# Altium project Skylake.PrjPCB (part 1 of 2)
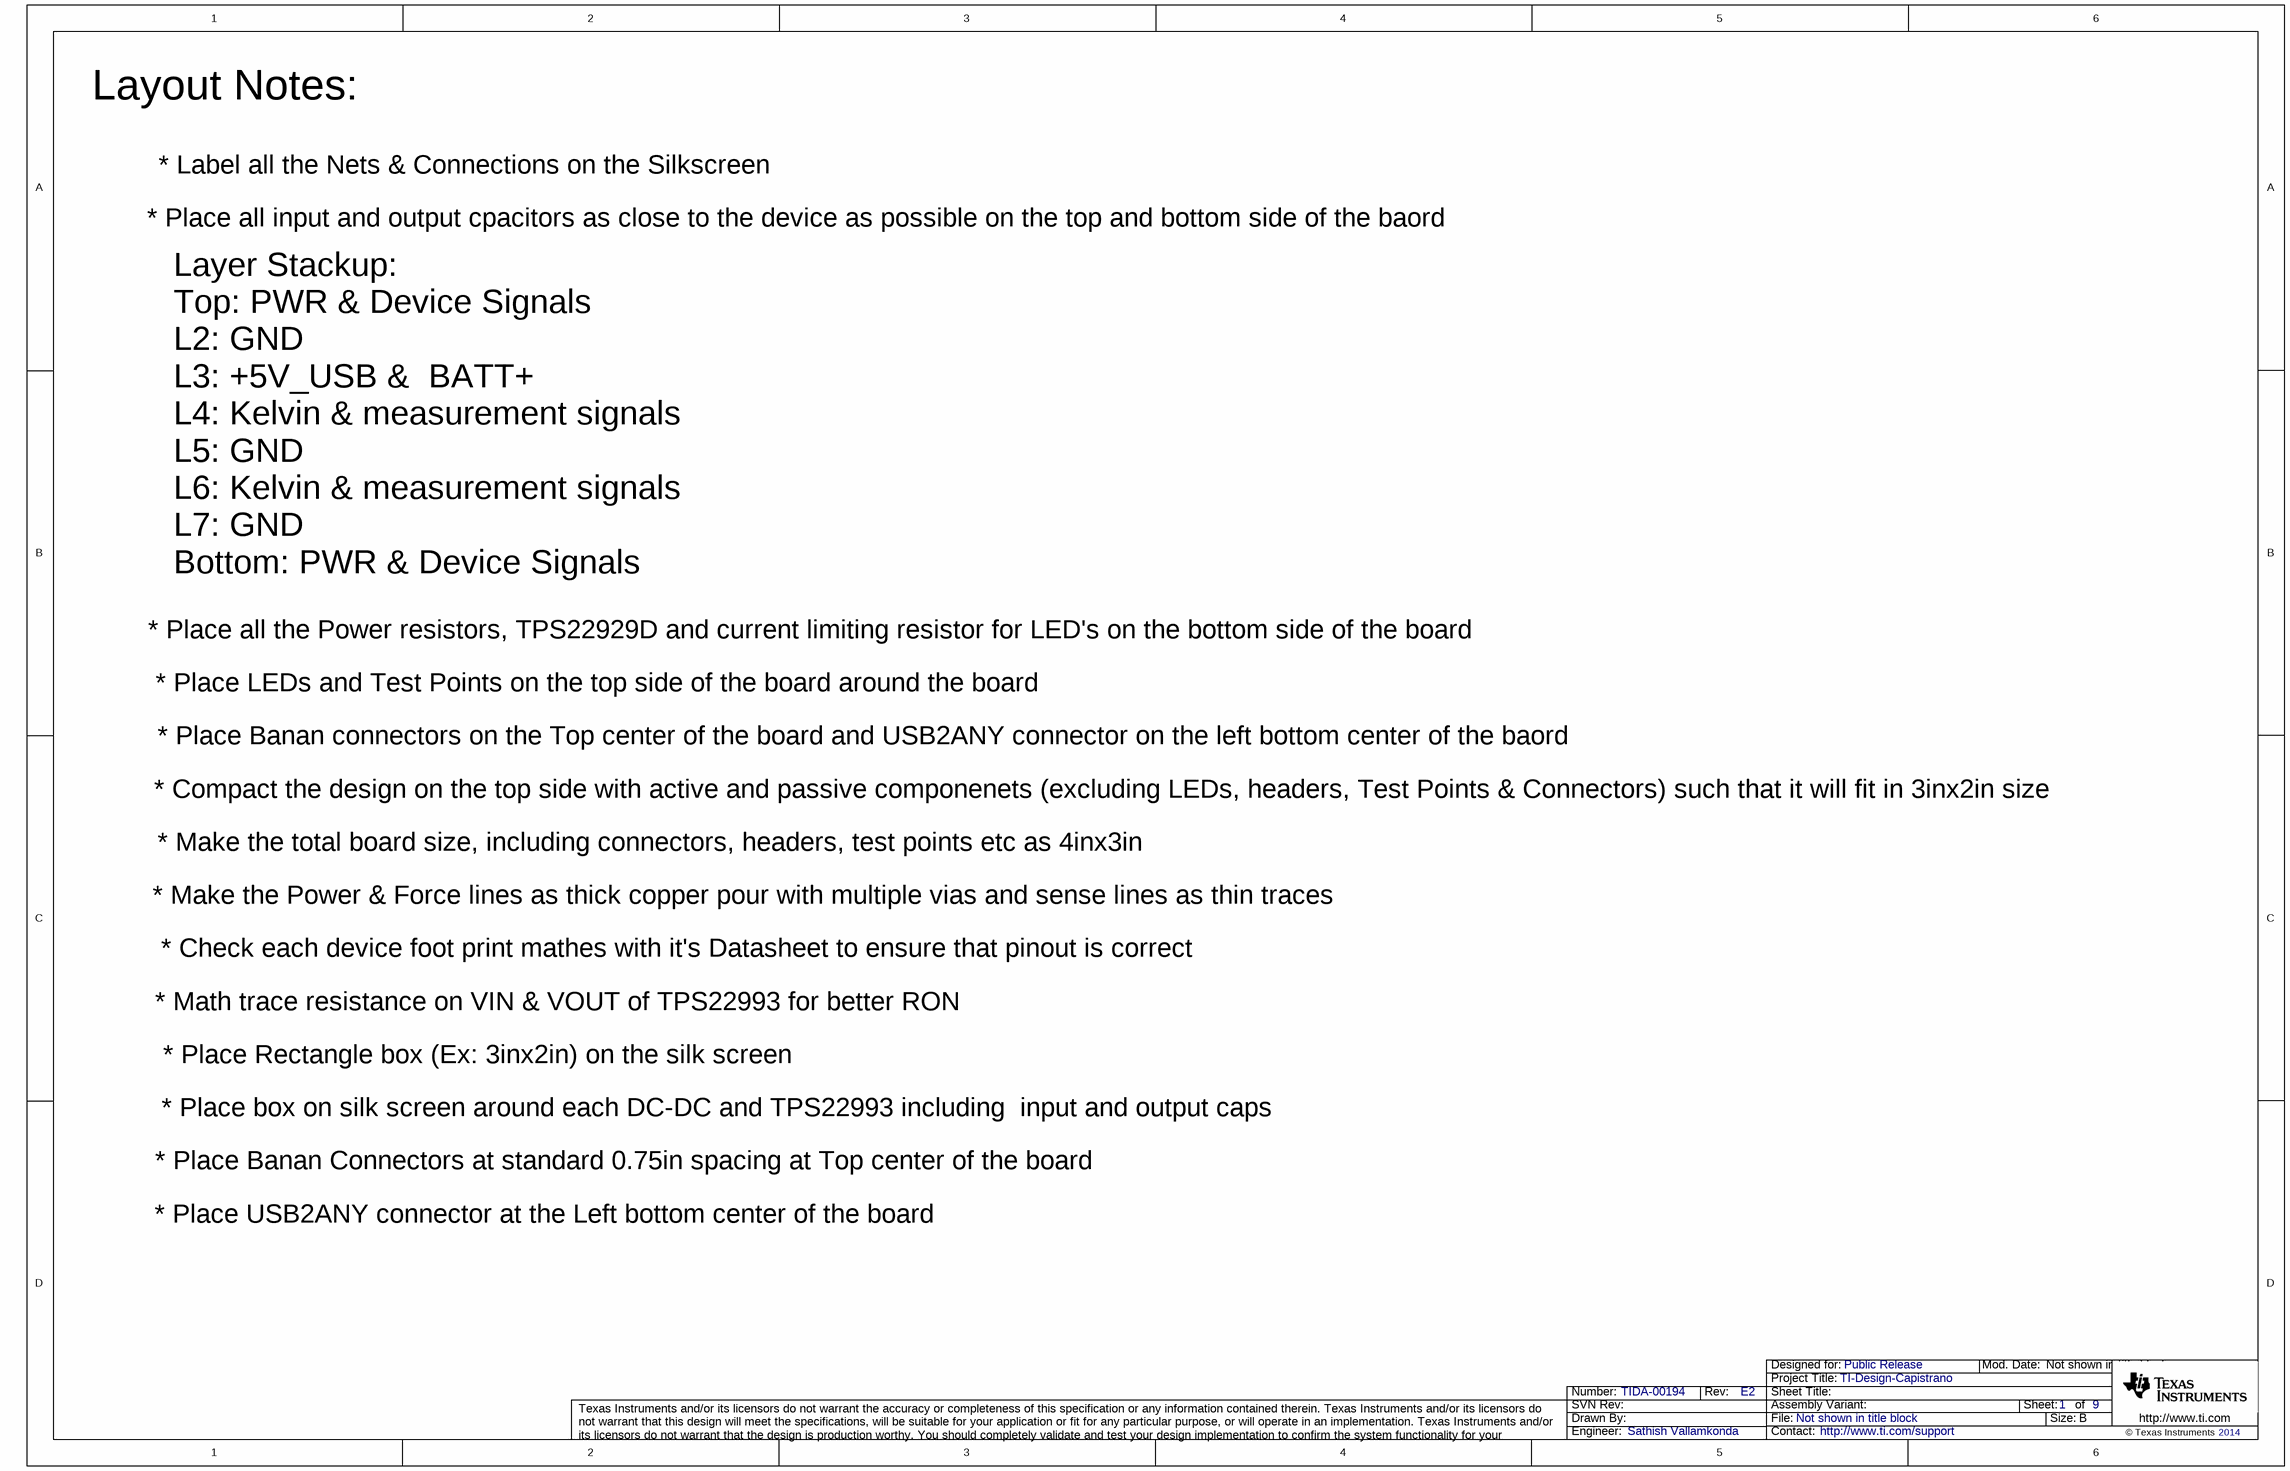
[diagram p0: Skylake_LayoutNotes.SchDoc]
CopyrightYear: 2014; PCB_Layout: Pactron; PCB_Rev: E2; PRJ_Customer: Public Release; PRJ_Engineer: Sathish Vallamkonda; PRJ_Number: TIDA-00194; PRJ_Title: TI-Design-Capistrano; SCH_Rev: E2; TechSupport: http://www.ti.com/support
9 sheets, 344 parts. Net scope: flat (ports and power ports of the same name join across sheets).
Board file: Skylake.PcbDoc
Sheets:
  Skylake_LayoutNotes.SchDoc
  Skylake_Hardware.SchDoc
  Skylake_USB2ANY_connections.SchDoc
  Skylake_TPS22993_U1_U2.SchDoc
  Skylake_TPS22993_U3_U4.SchDoc
  Skylake_TPS22993_U5_U6.SchDoc
  Skylake_TPS22993_U7.SchDoc
  Skylake_LEDs_1.SchDoc
  Skylake_LEDs_2.SchDoc

## Sheet Skylake_LayoutNotes.SchDoc
size 431 x 279 mm; Date: Not shown in title block; ApprovedBy: Not shown in title block; CheckedBy: Not shown in title block; Author: Not shown in title block; CompanyName: Not shown in title block; Engineer: Not shown in title block; Organization: Not shown in title block; Address1: Not shown in title block; Address2: Not shown in title block; Address3: Not shown in title block; Address4: Not shown in title block; DocumentNumber: 1; Revision: Use project parameter SCH_Rev; SheetNumber: 1; SheetTotal: 9; PageSetup: Record=PageOptions|CenterHorizontal=True|CenterVertical=True|PrintScale=1.00|XCorrection=1.00|YCorrection=1.00|PrintKind=0|BorderSize=5000000|LeftOffset=0|BottomOffset=0|Orientation=2|PaperLength=1000|PaperWidth=1000|Scale=100|PaperSource=15|PrintQuality=600|MediaType=1|DitherType=10|PaperKind=Letter|PrintScaleMode=1

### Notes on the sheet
- Layout Notes:
- * Label all the Nets & Connections on the Silkscreen
- * Place all input and output cpacitors as close to the device as possible on the top and bottom side of the baord
- Layer Stackup:
  Top: PWR & Device Signals
  L2: GND
  L3: +5V_USB &  BATT+
  L4: Kelvin & measurement signals
  L5: GND
  L6: Kelvin & measurement signals
  L7: GND
  Bottom: PWR & Device Signals
- * Place all the Power resistors, TPS22929D and current limiting resistor for LED's on the bottom side of the board
- * Place LEDs and Test Points on the top side of the board around the board
- * Place Banan connectors on the Top center of the board and USB2ANY connector on the left bottom center of the baord
- * Compact the design on the top side with active and passive componenets (excluding LEDs, headers, Test Points & Connectors) such that it will fit in 3inx2in size
- * Make the total board size, including connectors, headers, test points etc as 4inx3in
- * Make the Power & Force lines as thick copper pour with multiple vias and sense lines as thin traces
- * Check each device foot print mathes with it's Datasheet to ensure that pinout is correct
- * Math trace resistance on VIN & VOUT of TPS22993 for better RON
- * Place Rectangle box (Ex: 3inx2in) on the silk screen
- * Place Banan Connectors at standard 0.75in spacing at Top center of the board
- * Place box on silk screen around each DC-DC and TPS22993 including  input and output caps
- * Place USB2ANY connector at the Left bottom center of the board

## Sheet Skylake_Hardware.SchDoc
size 431 x 279 mm; Date: Not shown in title block; ApprovedBy: Not shown in title block; CheckedBy: Not shown in title block; Author: Not shown in title block; CompanyName: Not shown in title block; Engineer: Not shown in title block; Organization: Not shown in title block; Address1: Not shown in title block; Address2: Not shown in title block; Address3: Not shown in title block; Address4: Not shown in title block; DocumentNumber: 1; Revision: Use project parameter SCH_Rev; SheetNumber: 2; SheetTotal: 9; PageSetup: Record=PageOptions|CenterHorizontal=True|CenterVertical=True|PrintScale=1.00|XCorrection=1.00|YCorrection=1.00|PrintKind=0|BorderSize=5000000|LeftOffset=0|BottomOffset=0|Orientation=2|PaperLength=1000|PaperWidth=1000|Scale=100|PaperSource=15|PrintQuality=600|MediaType=1|DitherType=10|PaperKind=Letter|PrintScaleMode=1
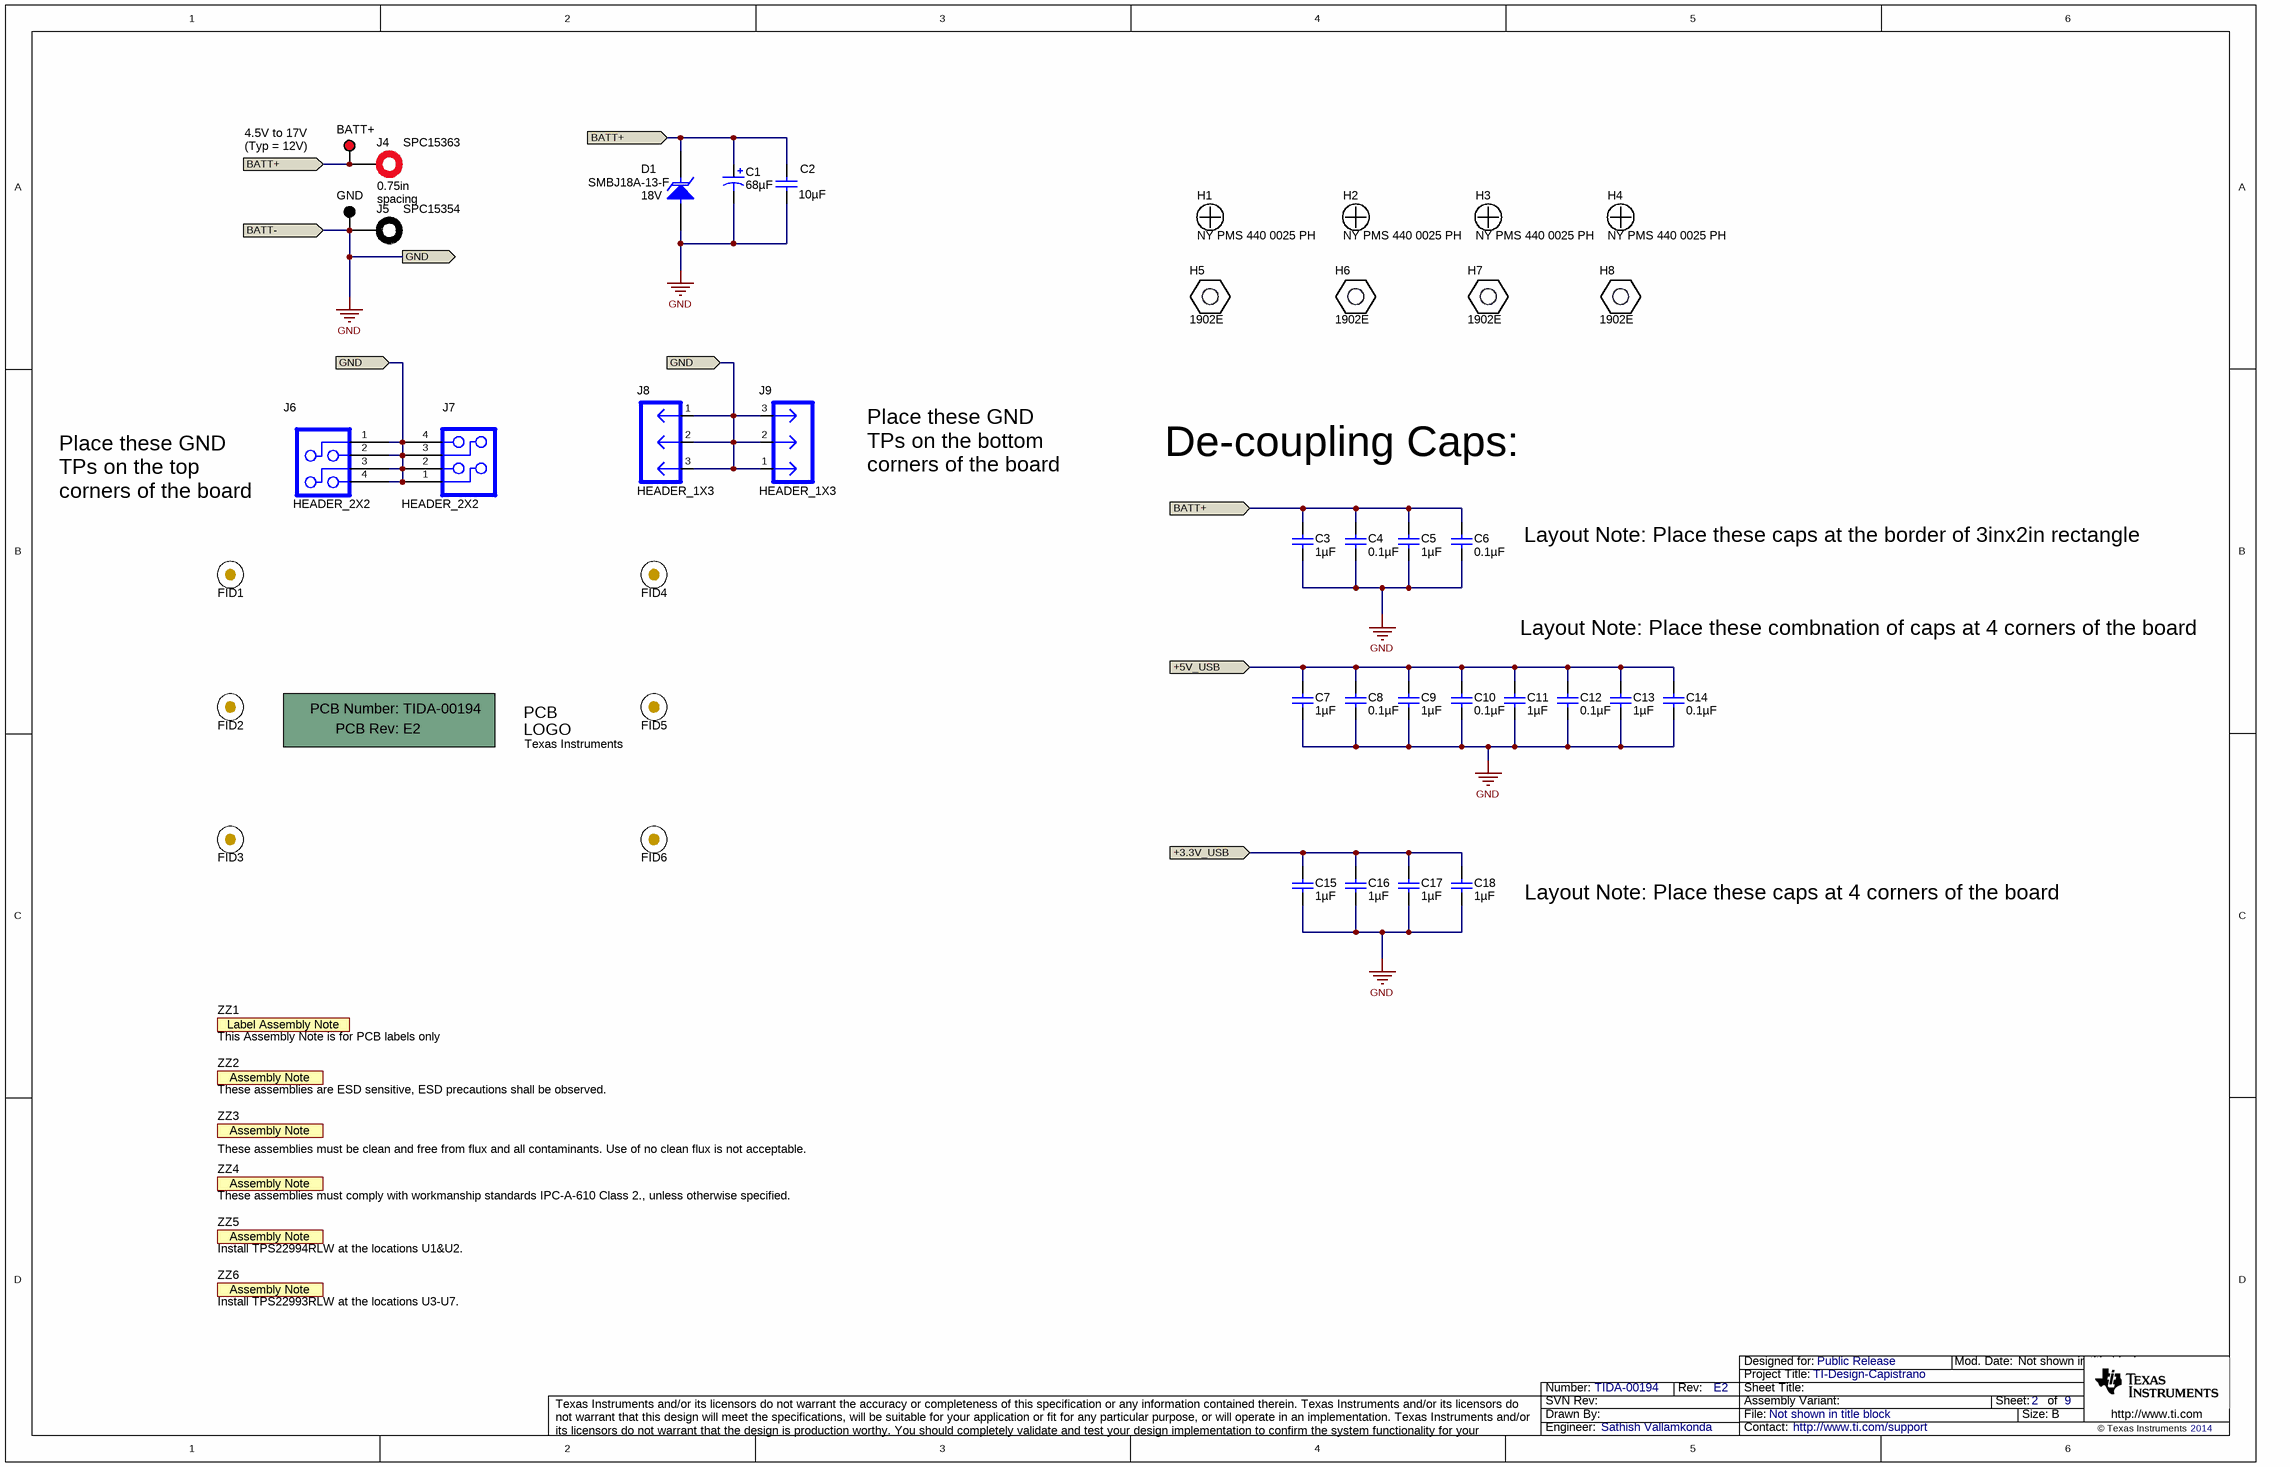
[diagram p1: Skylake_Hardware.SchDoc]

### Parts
!PCB  Printed Circuit Board  (value not drawn)  (mechanical)
BATT+  5005  [Keystone5005]  (value not drawn)
C1  ValueDisplayed: 68µF  [7361-38]  (hidden comment: TPSV686M035R0150)
C2  ValueDisplayed: 10µF  [1210]  (hidden comment: C3225X6S1V106K250AC)
C3  ValueDisplayed: 1µF  [0805_HV]  (hidden comment: C1608X7R1V105K080AC)
C4  ValueDisplayed: 0.1µF  [0805_HV]  (hidden comment: Taiyo Yuden)
C5  ValueDisplayed: 1µF  [0805_HV]  (hidden comment: C1608X7R1V105K080AC)
C6  ValueDisplayed: 0.1µF  [0805_HV]  (hidden comment: Taiyo Yuden)
C7  ValueDisplayed: 1µF  [0805_HV]  (hidden comment: 0805ZC105KAT2A)
C8  ValueDisplayed: 0.1µF  [0603]  (hidden comment: C0603C104K8RACTU)
C9  ValueDisplayed: 1µF  [0805_HV]  (hidden comment: 0805ZC105KAT2A)
C10  ValueDisplayed: 0.1µF  [0603]  (hidden comment: C0603C104K8RACTU)
C11  ValueDisplayed: 1µF  [0805_HV]  (hidden comment: 0805ZC105KAT2A)
C12  ValueDisplayed: 0.1µF  [0603]  (hidden comment: C0603C104K8RACTU)
C13  ValueDisplayed: 1µF  [0805_HV]  (hidden comment: 0805ZC105KAT2A)
C14  ValueDisplayed: 0.1µF  [0603]  (hidden comment: C0603C104K8RACTU)
C15  ValueDisplayed: 1µF  [0805_HV]  (hidden comment: 0805ZC105KAT2A)
C16  ValueDisplayed: 1µF  [0805_HV]  (hidden comment: 0805ZC105KAT2A)
C17  ValueDisplayed: 1µF  [0805_HV]  (hidden comment: 0805ZC105KAT2A)
C18  ValueDisplayed: 1µF  [0805_HV]  (hidden comment: 0805ZC105KAT2A)
D1  SMBJ18A-13-F  value 18V  [SMB]
FID1  Fiducial  [Fiducial10-20]  (value not drawn)
FID2  Fiducial  [Fiducial10-20]  (value not drawn)
FID3  Fiducial  [Fiducial10-20]  (value not drawn)
FID4  Fiducial  [Fiducial10-20]  (value not drawn)
FID5  Fiducial  [Fiducial10-20]  (value not drawn)
FID6  Fiducial  [Fiducial10-20]  (value not drawn)
GND  5006  [Keystone5006]  (value not drawn)
H1  NY PMS 440 0025 PH  [NY PMS 440 0025 PH]
H2  NY PMS 440 0025 PH  [NY PMS 440 0025 PH]
H3  NY PMS 440 0025 PH  [NY PMS 440 0025 PH]
H4  NY PMS 440 0025 PH  [NY PMS 440 0025 PH]
H5  1902E  [Keystone_1902E]
H6  1902E  [Keystone_1902E]
H7  1902E  [Keystone_1902E]
H8  1902E  [Keystone_1902E]
J4  SPC15363  [Tenma_SPC15363]
J5  SPC15354  [Tenma_SPC15354]
J6  HEADER_2X2  [HDR_2X2]
J7  HEADER_2X2  [HDR_2X2]
J8  HEADER_1X3  [HDR100_1X3]
J9  HEADER_1X3  [HDR100_1X3]
Logo1  Texas Instruments  [TI_Stacked_Overlay_Small]  (no BOM)
ZZ1  This Assembly Note is for PCB labels only  [AssemblyNoteLabel]  (no BOM)
ZZ2  These assemblies are ESD sensitive, ESD precautions shall be observed.  [AssemblyNote]  (no BOM)
ZZ3  These assemblies must be clean and free from flux and all contaminants. Use of no clean flux is not acceptable.  [AssemblyNote]  (no BOM)
ZZ4  These assemblies must comply with workmanship standards IPC-A-610 Class 2., unless otherwise specified.  [AssemblyNote]  (no BOM)
ZZ5  Install TPS22994RLW at the locations U1&U2.  [AssemblyNote]  (no BOM)
ZZ6  Install TPS22993RLW at the locations U3-U7.  [AssemblyNote]  (no BOM)

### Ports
+3.3V_USB (in), +5V_USB (in), BATT+ (in), BATT- (in), GND (in), GND (out)

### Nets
GND: C1.2(-) C2.2 C3.2 C4.2 C5.2 C6.2 C7.2 C8.2 C9.2 C10.2 C11.2 C12.2 C13.2 C14.2 C15.2 C16.2 C17.2 C18.2 D1.2(A) GND.1 J5.1 J6.1 J6.2 J6.3 J6.4 J7.1 J7.2 J7.3 J7.4 J8.1 J8.2 J8.3 J9.1 J9.2 J9.3 ; port BATT-, port GND
+3.3V_USB: C15.1 C16.1 C17.1 C18.1 ; port +3.3V_USB
+5V_USB: C7.1 C8.1 C9.1 C10.1 C11.1 C12.1 C13.1 C14.1 ; port +5V_USB
BATT+: BATT+.1 C1.1(+) C2.1 C3.1 C4.1 C5.1 C6.1 D1.1(K) J4.1 ; port BATT+

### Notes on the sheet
- (near BATT+) 4.5V to 17V
  (Typ = 12V)
- (near J4) 0.75in spacing
- Place these GND TPs on the bottom corners of the board
- De-coupling Caps:
- Place these GND TPs on the top corners of the board
- (near C6) Layout Note: Place these caps at the border of 3inx2in rectangle
- Layout Note: Place these combnation of caps at 4 corners of the board
- (near C18) Layout Note: Place these caps at 4 corners of the board

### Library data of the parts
!PCB = PCB: Manufacturer: Any; PartNumber: TIDA-00194; SymbolCreator: a0412235
BATT+ = 5005: Test Point, Compact, Red, TH; Manufacturer: Keystone; CompType: Test Point Loop; U/M: EA
C1 = TPSV686M025R0095: CAP, TA, 68uF, 35V, +/-20%, 0.095 ohm, SMD; Manufacturer: AVX; Polarized: Y; CompType: Capacitor; U/M: EA; Cap_F: 0.000068; Tolerance_%: 20; VDC_V: 35; ESR_Ohm: 0.095; IRMS_A: 1.46; TaMin_C: -55; TaMax_C: 125; Cap_Case: V
C2 = GRM32DR61E106KA12L: CAP, CERM, 10uF, 35V, +/-10%, X5R, 1210; Manufacturer: TDK Corporation; Polarized: N; CompType: Capacitor; U/M: EA; Cap_F: 0.00001; Tolerance_%: 10; Value1: Unknown; VDC_V: 35; TaMin_C: -55; TaMax_C: 85
C3 C5 = GRM21BR61E226ME44: CAP, CERM, 1uF, 35V, +/-20%, X5R, 0805; Manufacturer: TDK Corporation; Polarized: N; CompType: Capacitor; U/M: EA; Cap_F: 0.000022; Tolerance_%: 20; Value1: Unknown; VDC_V: 35; TaMin_C: -55; TaMax_C: 85; Cap_Case: 0805
C4 C6 = GRM21BR61E226ME44: CAP, CERM, 0.1uF, 35V, +/-20%, X5R, 0603; Manufacturer: TDK Corporation; Polarized: N; CompType: Capacitor; U/M: EA; Tolerance_%: 20; Value1: Unknown; VDC_V: 35; TaMin_C: -55; TaMax_C: 85; Cap_Case: 0603
C7 C9 C11 C13 C15-C18 = 0805ZC105KAT2A: CAP, CERM, 1uF, 10V, +/-10%, X7R, 0805; Manufacturer: AVX; Polarized: N; CompType: Capacitor; U/M: EA; Cap_F: 0.000001; Tolerance_%: 10; ESR_Ohm: 0.008; Value1: 0.008 ohm; TaMin_C: -55; TaMax_C: 125; Cap_Case: 0805
C8 C10 C12 C14 = GRM188R71C104KA01D: CAP, CERM, 0.1uF, 10V, +/-10%, X7R, 0603; Manufacturer: Kemet; Polarized: N; CompType: Capacitor; U/M: EA; Cap_F: 0.0000001; Tolerance_%: 10; Value1: Unknown; TaMin_C: -55; TaMax_C: 125
D1 = SMBJ18A-13-F: Diode, TVS, Uni, 18V, 600W, SMB; Manufacturer: Diodes Inc.; U/M: EA; Power_W: 5; Vr_V: 18; Value1: 5W
FID1-FID6 = Fiducial: Fiducial mark.  There is nothing to buy or mount.; SymbolCreator: codlsc
GND = 5006: Test Point, Compact, Black, TH; Manufacturer: Keystone; CompType: Test Point Loop; U/M: EA
H1-H4 = NY PMS 440 0025 PH: Machine Screw, Round, #4-40 x 1/4, Nylon, Philips panhead; Manufacturer: B&F Fastener Supply; CompType: Hardware; SymbolCreator: codlsc; U/M: EA
H5-H8 = 1902E: Standoff, Hex, 1"L #4-40 Nylon; Manufacturer: Keystone; SymbolCreator: a0412235; CompType: Hardware
J4 = SPC15363: BANANA JACK, SOLDER LUG, RED, TH; Manufacturer: Tenma; SymbolCreator: a0412235; U/M: EA
J5 = SPC15354: BANANA JACK, SOLDER LUG, BLACK, TH; Manufacturer: Tenma; SymbolCreator: a0412235; U/M: EA
J6 J7 = HEADER_2X2: Header, 2x2-pin, 100mil spacing; Manufacturer: Sullins; PartNumber: PEC02DAAN; area: 40000; Value: PEC02DAAN
J8 J9 = HEADER_1X3: Header, Male 3-pin, 100mil spacing,; Manufacturer: Sullins; PartNumber: PEC03SAAN; area: 30000; Value: PEC03SAAN
Logo1 = TI_Logo: Texas Instrument Corporate Signature; SymbolCreator: codlsc
ZZ1 = AssemblyNoteLabel: SymbolCreator: a0412235
ZZ2-ZZ4 = AssemblyNote: SymbolCreator: codlsc
ZZ5 ZZ6 = AssemblyNote: These assemblies must comply with workmanship standards IPC-A-610 Class 2., unless otherwise specified.; SymbolCreator: codlsc

## Sheet Skylake_USB2ANY_connections.SchDoc
size 431 x 279 mm; Date: Not shown in title block; ApprovedBy: Not shown in title block; CheckedBy: Not shown in title block; Author: Not shown in title block; CompanyName: Not shown in title block; Engineer: Not shown in title block; Organization: Not shown in title block; Address1: Not shown in title block; Address2: Not shown in title block; Address3: Not shown in title block; Address4: Not shown in title block; DocumentNumber: 1; Revision: Use project parameter SCH_Rev; SheetNumber: 3; SheetTotal: 9; PageSetup: Record=PageOptions|CenterHorizontal=True|CenterVertical=True|PrintScale=1.00|XCorrection=1.00|YCorrection=1.00|PrintKind=0|BorderSize=5000000|LeftOffset=0|BottomOffset=0|Orientation=2|PaperLength=1000|PaperWidth=1000|Scale=100|PaperSource=15|PrintQuality=600|MediaType=1|DitherType=10|PaperKind=Letter|PrintScaleMode=1
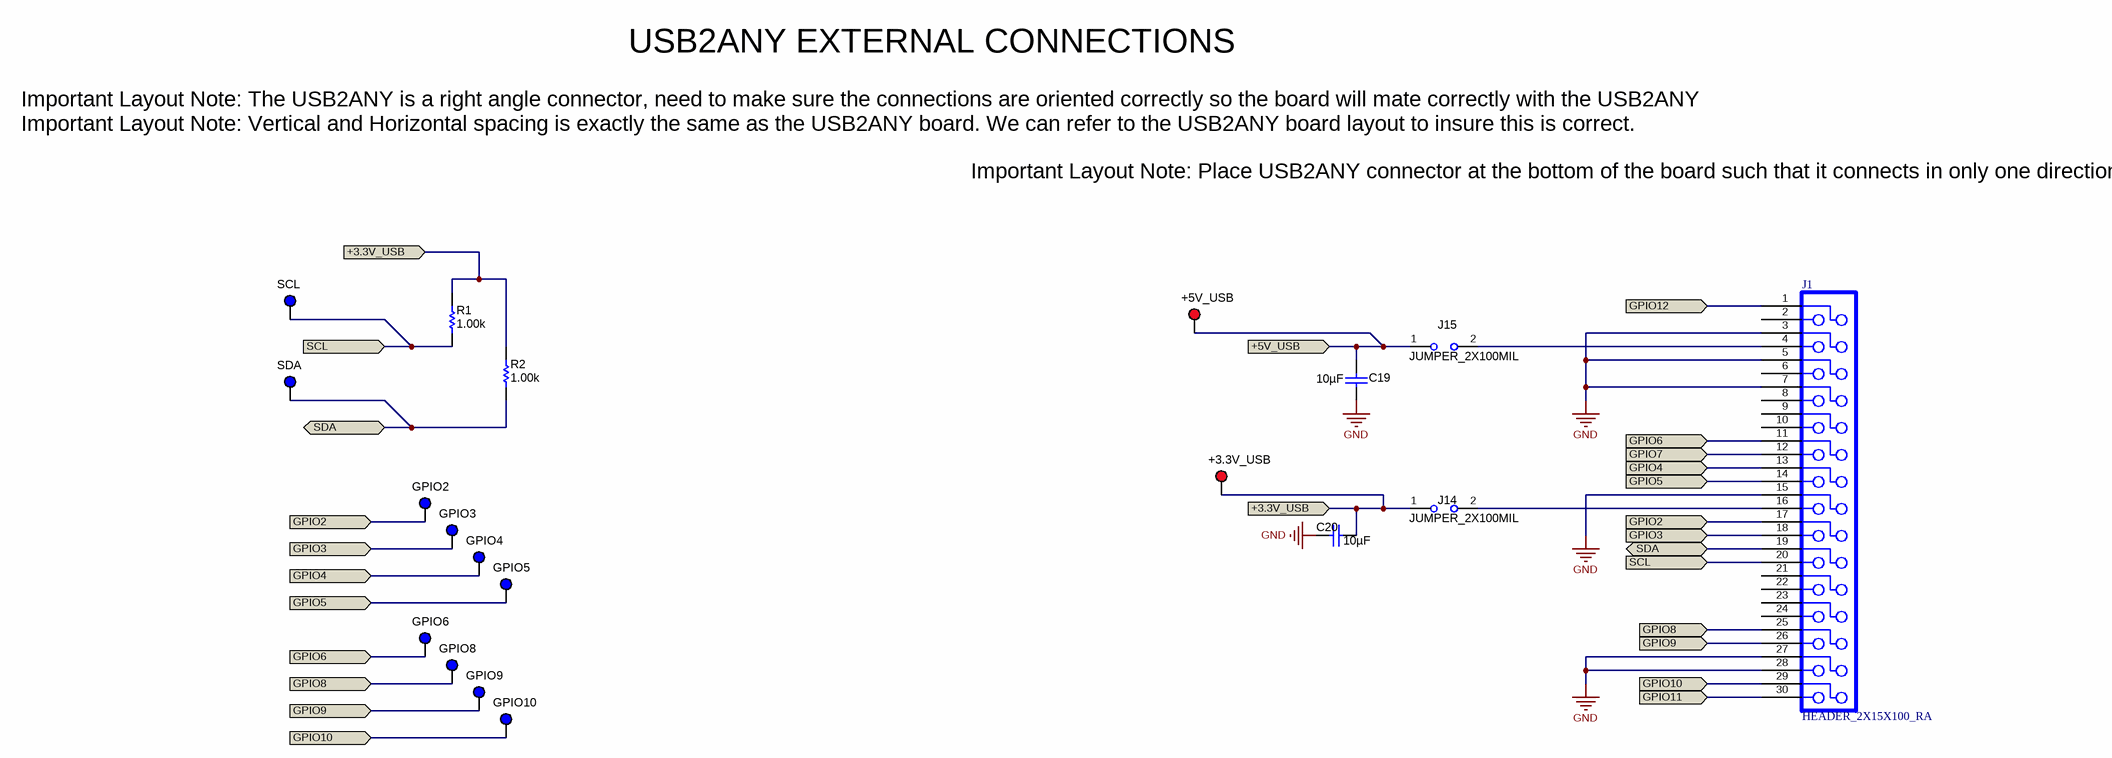
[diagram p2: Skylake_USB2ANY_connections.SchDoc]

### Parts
+3.3V_USB  5005  [Keystone5005]  (value not drawn)
+5V_USB  5005  [Keystone5005]  (value not drawn)
C19  ValueDisplayed: 10µF  [0805_HV]  (hidden comment: C0805C106K8PACTU)
C20  ValueDisplayed: 10µF  [0805_HV]  (hidden comment: C0805C106K8PACTU)
GPIO2  5122  [Keystone5122]  (value not drawn)
GPIO3  5122  [Keystone5122]  (value not drawn)
GPIO4  5122  [Keystone5122]  (value not drawn)
GPIO5  5122  [Keystone5122]  (value not drawn)
GPIO6  5122  [Keystone5122]  (value not drawn)
GPIO8  5122  [Keystone5122]  (value not drawn)
GPIO9  5122  [Keystone5122]  (value not drawn)
GPIO10  5122  [Keystone5122]  (value not drawn)
J1  HEADER_2X15X100_RA  [2530-5002UB]
J14  JUMPER_2X100MIL  [HDR100_1X2]
J15  JUMPER_2X100MIL  [HDR100_1X2]
R1  value 1.00k  [0402]  (hidden comment: CRCW04021K00FKED)
R2  value 1.00k  [0402]  (hidden comment: CRCW04021K00FKED)
SCL  5122  [Keystone5122]  (value not drawn)
SDA  5122  [Keystone5122]  (value not drawn)

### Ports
+3.3V_USB (in), +5V_USB (in), GPIO2 (in), GPIO3 (in), GPIO4 (in), GPIO5 (in), GPIO6 (in), GPIO7 (in), GPIO8 (in), GPIO9 (in), GPIO10 (in), GPIO11 (in), GPIO12 (in), SCL (in), SDA (bidir)

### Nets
GND: C19.2 C20.2 J1.3 J1.5 J1.7 J1.15 J1.27 J1.28
+3.3V_USB: +3.3V_USB.1 C20.1 J14.1 R1.2 R2.2 ; port +3.3V_USB
+5V_USB: +5V_USB.1 C19.1 J15.1 ; port +5V_USB
GPIO2: GPIO2.1 J1.17 ; port GPIO2
GPIO3: GPIO3.1 J1.18 ; port GPIO3
GPIO4: GPIO4.1 J1.13 ; port GPIO4
GPIO5: GPIO5.1 J1.14 ; port GPIO5
GPIO6: GPIO6.1 J1.11 ; port GPIO6
GPIO7: J1.12 ; port GPIO7
GPIO8: GPIO8.1 J1.25 ; port GPIO8
GPIO9: GPIO9.1 J1.26 ; port GPIO9
GPIO10: GPIO10.1 J1.29 ; port GPIO10
GPIO11: J1.30 ; port GPIO11
GPIO12: J1.1 ; port GPIO12
SCL: J1.20 R1.1 SCL.1 ; port SCL
SDA: J1.19 R2.1 SDA.1 ; port SDA
NetJ1_4: J1.4 J15.2
NetJ1_16: J1.16 J14.2

Not connected (* = marked no-connect by the designer): J1 2 6 8 9 10 21 22 23 24

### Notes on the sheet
- USB2ANY EXTERNAL CONNECTIONS
- Important Layout Note: The USB2ANY is a right angle connector, need to make sure the connections are oriented correctly so the board will mate correctly with the USB2ANY
  Important Layout Note: Vertical and Horizontal spacing is exactly the same as the USB2ANY board. We can refer to the USB2ANY board layout to insure this is correct.
- Important Layout Note: Place USB2ANY connector at the bottom of the board such that it connects in only one direction

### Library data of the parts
+3.3V_USB +5V_USB = 5005: as BATT+ on sheet Skylake_Hardware
C19 C20 = C0805C106K8PACTU: CAP, CERM, 10uF, 10V, +/-10%, X5R, 0805; Manufacturer: Kemet; Polarized: N; CompType: Capacitor; U/M: EA; Cap_F: 0.00001; Tolerance_%: 10; ESR_Ohm: 0.003; Value1: 0.003 ohm; IRMS_A: 11.43; TaMin_C: -55; TaMax_C: 85; Cap_Case: 0805
GPIO2-GPIO6 GPIO8-GPIO10 SCL SDA = 5122: Test Point, Compact, Blue, TH; Manufacturer: Keystone; CompType: Test Point Loop; U/M: EA
J1 = HEADER_2X15X100_RA: Header, Male 2x15-pin,  100mil spacing (36-pin strip), Right-Angle; Manufacturer: 3M; area: 872100; Value: 2530-5002UB
J14 J15 = JUMPER_2X100MIL: Header, Male 2-pin, 100mil spacing,; Manufacturer: Sullins; PartNumber: PEC02SAAN; area: 20000; Value: PEC02SAAN
R1 R2 = CRCW04021K00FKED: RES, 1.00k ohm, 1%, 0.063W, 0402; Manufacturer: Vishay-Dale; CompType: Resistor; Res_ohm: 1000; Value_Code: 1k00; Tolerance_%: 1; Power_W: 0.063; VDC_V: 50; TempCo: 100 ppm/C; EIA_Code: E96; U/M: EA

## Sheet Skylake_TPS22993_U1_U2.SchDoc
size 431 x 279 mm; Date: Not shown in title block; ApprovedBy: Not shown in title block; CheckedBy: Not shown in title block; Author: Not shown in title block; CompanyName: Not shown in title block; Engineer: Not shown in title block; Organization: Not shown in title block; Address1: Not shown in title block; Address2: Not shown in title block; Address3: Not shown in title block; Address4: Not shown in title block; DocumentNumber: 1; Revision: Use project parameter SCH_Rev; SheetNumber: 4; SheetTotal: 9; PageSetup: Record=PageOptions|CenterHorizontal=True|CenterVertical=True|PrintScale=1.00|XCorrection=1.00|YCorrection=1.00|PrintKind=0|BorderSize=5000000|LeftOffset=0|BottomOffset=0|Orientation=2|PaperLength=1000|PaperWidth=1000|Scale=100|PaperSource=15|PrintQuality=600|MediaType=1|DitherType=10|PaperKind=Letter|PrintScaleMode=1
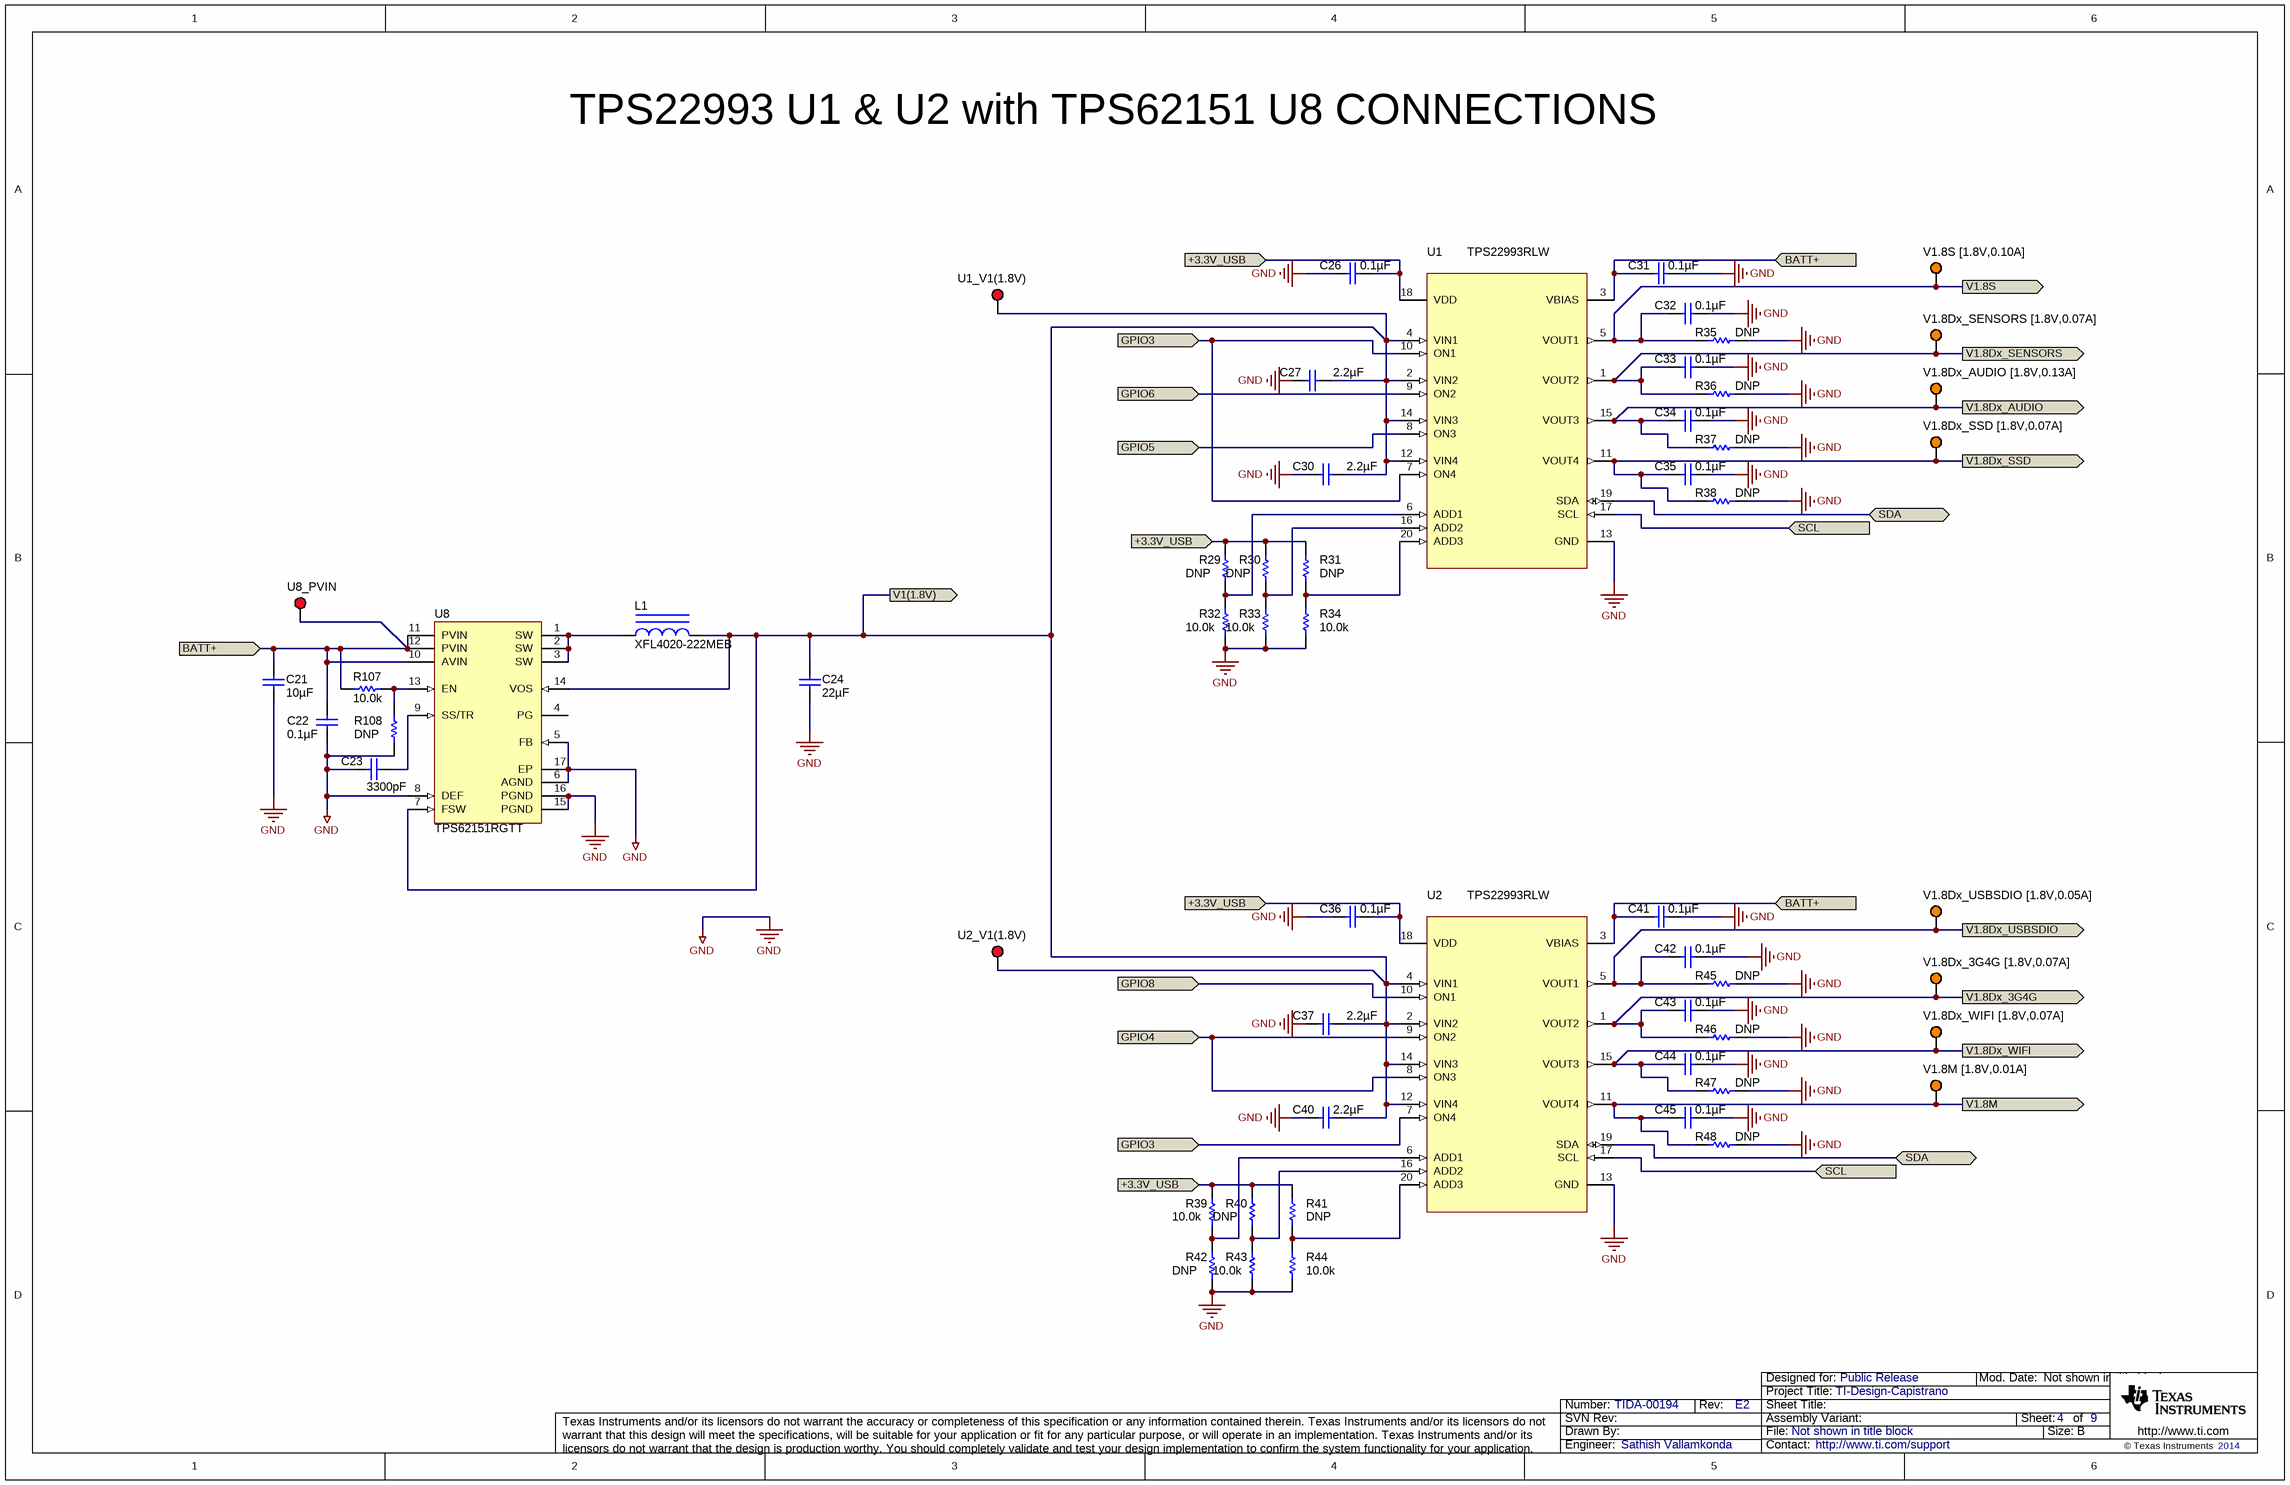
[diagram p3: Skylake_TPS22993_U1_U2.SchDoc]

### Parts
C21  ValueDisplayed: 10µF  [0805_HV]  (hidden comment: C2012JB1V106K085AC)
C22  ValueDisplayed: 0.1µF  [0805_HV]  (hidden comment: Taiyo Yuden)
C23  ValueDisplayed: 3300pF  [0603]  (hidden comment: C0603C332J3RACTU)
C24  ValueDisplayed: 22µF  [0805_HV]  (hidden comment: C2012X5R1V226M125AC)
C26  ValueDisplayed: 0.1µF  [0603]  (hidden comment: C0603C104K8RACTU)
C27  ValueDisplayed: 2.2µF  [0603]  (hidden comment: GRM188C81A225KE34D)
C30  ValueDisplayed: 2.2µF  [0603]  (hidden comment: GRM188C81A225KE34D)
C31  ValueDisplayed: 0.1µF  [0805_HV]  (hidden comment: GMK212BJ104KGHT)
C32  ValueDisplayed: 0.1µF  [0603]  (hidden comment: C0603C104K8RACTU)
C33  ValueDisplayed: 0.1µF  [0603]  (hidden comment: C0603C104K8RACTU)
C34  ValueDisplayed: 0.1µF  [0603]  (hidden comment: C0603C104K8RACTU)
C35  ValueDisplayed: 0.1µF  [0603]  (hidden comment: C0603C104K8RACTU)
C36  ValueDisplayed: 0.1µF  [0603]  (hidden comment: C0603C104K8RACTU)
C37  ValueDisplayed: 2.2µF  [0603]  (hidden comment: GRM188C81A225KE34D)
C40  ValueDisplayed: 2.2µF  [0603]  (hidden comment: GRM188C81A225KE34D)
C41  ValueDisplayed: 0.1µF  [0805_HV]  (hidden comment: GMK212BJ104KGHT)
C42  ValueDisplayed: 0.1µF  [0603]  (hidden comment: C0603C104K8RACTU)
C43  ValueDisplayed: 0.1µF  [0603]  (hidden comment: C0603C104K8RACTU)
C44  ValueDisplayed: 0.1µF  [0603]  (hidden comment: C0603C104K8RACTU)
C45  ValueDisplayed: 0.1µF  [0603]  (hidden comment: C0603C104K8RACTU)
L1  XFL4020-222MEB  [XFL4020]
R29  value DNP  [0402]  (hidden comment: CRCW040210K0FKED)
R30  value DNP  [0402]  (hidden comment: CRCW040210K0FKED)
R31  value DNP  [0402]  (hidden comment: CRCW040210K0FKED)
R32  value 10.0k  [0402]  (hidden comment: CRCW040210K0FKED)
R33  value 10.0k  [0402]  (hidden comment: CRCW040210K0FKED)
R34  value 10.0k  [0402]  (hidden comment: CRCW040210K0FKED)
R35  value DNP  [1206]  (hidden comment: CRCW120618R0JNEA)
R36  value DNP  [1210M]  (hidden comment: ERJ-14NF25R5U)
R37  value DNP  [1210M]  (hidden comment: ERJ-14NF13R7U)
R38  value DNP  [1210M]  (hidden comment: ERJ-14NF25R5U)
R39  value 10.0k  [0402]  (hidden comment: CRCW040210K0FKED)
R40  value DNP  [0402]  (hidden comment: CRCW040210K0FKED)
R41  value DNP  [0402]  (hidden comment: CRCW040210K0FKED)
R42  value DNP  [0402]  (hidden comment: CRCW040210K0FKED)
R43  value 10.0k  [0402]  (hidden comment: CRCW040210K0FKED)
R44  value 10.0k  [0402]  (hidden comment: CRCW040210K0FKED)
R45  value DNP  [1206]  (hidden comment: CRCW120636R0JNEA)
R46  value DNP  [1210M]  (hidden comment: ERJ-14NF25R5U)
R47  value DNP  [1210M]  (hidden comment: ERJ-14NF25R5U)
R48  value DNP  [1206]  (hidden comment: CRCW1206180RJNEA)
R107  value 10.0k  [0402]  (hidden comment: CRCW040210K0FKED)
R108  value DNP  [0402]  (hidden comment: CRCW040210K0FKED)
U1  TPS22993RLW  [RLW0020A]
U1_V1(1.8V)  5005  [Keystone5005]  (value not drawn)
U2  TPS22993RLW  [RLW0020A]
U2_V1(1.8V)  5005  [Keystone5005]  (value not drawn)
U8  TPS62151RGTT  [RGT0016C]
U8_PVIN  5005  [Keystone5005]  (value not drawn)
V1.8Dx_3G4G_[1.8V,0.07A]  5008  [Keystone5008]  (value not drawn)
V1.8Dx_AUDIO_[1.8V,0.13A]  5008  [Keystone5008]  (value not drawn)
V1.8Dx_SENSORS_[1.8V,0.07A]  5008  [Keystone5008]  (value not drawn)
V1.8Dx_SSD_[1.8V,0.07A]  5008  [Keystone5008]  (value not drawn)
V1.8Dx_USBSDIO_[1.8V,0.05A]  5008  [Keystone5008]  (value not drawn)
V1.8Dx_WIFI_[1.8V,0.07A]  5008  [Keystone5008]  (value not drawn)
V1.8M_[1.8V,0.01A]  5008  [Keystone5008]  (value not drawn)
V1.8S_[1.8V,0.10A]  5008  [Keystone5008]  (value not drawn)

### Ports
+3.3V_USB (in), BATT+ (in), GPIO3 (in), GPIO4 (in), GPIO5 (in), GPIO6 (in), GPIO8 (in), SCL (in), SDA (bidir), V1(1.8V) (out), V1.8Dx_3G4G (out), V1.8Dx_AUDIO (out), V1.8Dx_SENSORS (out), V1.8Dx_SSD (out), V1.8Dx_USBSDIO (out), V1.8Dx_WIFI (out), V1.8M (out), V1.8S (out)

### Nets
GND: C21.2 C22.2 C23.2 C24.2 C26.2 C27.2 C30.2 C31.1 C32.1 C33.1 C34.1 C35.1 C36.2 C37.2 C40.2 C41.1 C42.1 C43.1 C44.1 C45.1 R32.1 R33.1 R34.1 R35.2 R36.2 R37.2 R38.2 R42.1 R43.1 R44.1 R45.2 R46.2 R47.2 R48.2 R108.1 U1.13(GND) U2.13(GND) U8.5(FB) U8.6(AGND) U8.8(DEF) U8.15(PGND) U8.16(PGND) U8.17(EP)
+3.3V_USB: C26.1 C36.1 R29.2 R30.2 R31.2 R39.2 R40.2 R41.2 U1.18(VDD) U2.18(VDD) ; port +3.3V_USB
BATT+: C21.1 C22.1 C31.2 C41.2 R107.1 U1.3(VBIAS) U2.3(VBIAS) U8.10(AVIN) U8.11(PVIN) U8.12(PVIN) U8_PVIN.1 ; port BATT+
GPIO3: U1.7(ON4) U1.10(ON1) U2.7(ON4) ; port GPIO3
GPIO4: U2.8(ON3) U2.9(ON2) ; port GPIO4
GPIO5: U1.8(ON3) ; port GPIO5
GPIO6: U1.9(ON2) ; port GPIO6
GPIO8: U2.10(ON1) ; port GPIO8
SCL: U1.17(SCL) U2.17(SCL) ; port SCL
SDA: U1.19(SDA) U2.19(SDA) ; port SDA
V1(1.8V): C24.1 C27.1 C30.1 C37.1 C40.1 L1.2 U1.2(VIN2) U1.4(VIN1) U1.12(VIN4) U1.14(VIN3) U1_V1(1.8V).1 U2.2(VIN2) U2.4(VIN1) U2.12(VIN4) U2.14(VIN3) U2_V1(1.8V).1 U8.7(FSW) U8.14(VOS) ; port V1(1.8V)
V1.8Dx_3G4G: C43.2 R46.1 U2.1(VOUT2) V1.8Dx_3G4G_[1.8V,0.07A].1 ; port V1.8Dx_3G4G
V1.8Dx_AUDIO: C34.2 R37.1 U1.15(VOUT3) V1.8Dx_AUDIO_[1.8V,0.13A].1 ; port V1.8Dx_AUDIO
V1.8Dx_SENSORS: C33.2 R36.1 U1.1(VOUT2) V1.8Dx_SENSORS_[1.8V,0.07A].1 ; port V1.8Dx_SENSORS
V1.8Dx_SSD: C35.2 R38.1 U1.11(VOUT4) V1.8Dx_SSD_[1.8V,0.07A].1 ; port V1.8Dx_SSD
V1.8Dx_USBSDIO: C42.2 R45.1 U2.5(VOUT1) V1.8Dx_USBSDIO_[1.8V,0.05A].1 ; port V1.8Dx_USBSDIO
V1.8Dx_WIFI: C44.2 R47.1 U2.15(VOUT3) V1.8Dx_WIFI_[1.8V,0.07A].1 ; port V1.8Dx_WIFI
V1.8M: C45.2 R48.1 U2.11(VOUT4) V1.8M_[1.8V,0.01A].1 ; port V1.8M
V1.8S: C32.2 R35.1 U1.5(VOUT1) V1.8S_[1.8V,0.10A].1 ; port V1.8S
NetC23_1: C23.1 U8.9(SS/TR)
NetL1_1: L1.1 U8.1(SW) U8.2(SW) U8.3(SW)
NetR29_1: R29.1 R32.2 U1.6(ADD1)
NetR30_1: R30.1 R33.2 U1.16(ADD2)
NetR31_1: R31.1 R34.2 U1.20(ADD3)
NetR39_1: R39.1 R42.2 U2.6(ADD1)
NetR40_1: R40.1 R43.2 U2.16(ADD2)
NetR41_1: R41.1 R44.2 U2.20(ADD3)
NetR107_2: R107.2 R108.2 U8.13(EN)

Not connected (* = marked no-connect by the designer): U8 4(PG)

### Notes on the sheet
- TPS22993 U1 & U2 with TPS62151 U8 CONNECTIONS

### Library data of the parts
C21 = C2012X5R1E106K125AB: CAP, CERM, 10uF, 35V, +/-10%, X5R, 0805; Manufacturer: TDK; Polarized: N; CompType: Capacitor; U/M: EA; Cap_F: 0.00001; Tolerance_%: 10; Value1: Unknown; VDC_V: 35; TaMin_C: -55; TaMax_C: 85; Cap_Case: 0805
C22 = GRM21BR61E226ME44: as C4 on sheet Skylake_Hardware
C23 = C0603C332K5RACTU: CAP, CERM, 3300pF, 25V, +/-5%, X7R, 0603; Manufacturer: Kemet; Polarized: N; CompType: Capacitor; U/M: EA; Cap_F: 0.0000000033; Tolerance_%: 5; Value1: Unknown; VDC_V: 25; TaMin_C: -55; TaMax_C: 125
C24 = GRM21BR61E226ME44: CAP, CERM, 22uF, 35V, +/-20%, X5R, 0805; Manufacturer: TDK Corporation; Polarized: N; CompType: Capacitor; U/M: EA; Cap_F: 0.000022; Tolerance_%: 20; Value1: Unknown; VDC_V: 35; TaMin_C: -55; TaMax_C: 85; Cap_Case: 0805
C26 C32-C36 C42-C45 = GRM188R71C104KA01D: as C8 on sheet Skylake_Hardware
C27 C30 C37 C40 = GRM188C81A225KE34D: CAP, CERM, 2.2uF, 10V, +/-10%, X6S, 0603; Manufacturer: MuRata; Polarized: N; CompType: Capacitor; U/M: EA; Cap_F: 0.0000022; Tolerance_%: 10; Value1: Unknown; TaMin_C: -55; TaMax_C: 105
C31 C41 = GRM21BR61E226ME44: CAP, CERM, 0.1uF, 35V, +/-20%, X5R, 0805; Manufacturer: Taiyo Yuden; Polarized: N; CompType: Capacitor; U/M: EA; Cap_F: 0.000022; Tolerance_%: 20; Value1: Unknown; VDC_V: 35; TaMin_C: -55; TaMax_C: 85; Cap_Case: 0805
L1 = XFL4020-222MEB: Inductor, Shielded, Composite, 2.2uH, 3.7A, 0.02 ohm, SMD; Manufacturer: Coilcraft; Ind_H: 2.2E-6; ValueDisplayed: 2.2µH; Imax_A: 3.7; Irms: 8A @ 40C rise; Isat: 3.7A @ 30% inductance drop; DCR_ohm: 0.02; U/M: EA
R29-R31 R40-R42 R108 = CRCW040210K0FKED: RES, DNP, 1%, 0.063W, 0402; Manufacturer: Vishay-Dale; CompType: Resistor; Res_ohm: 10000; Value_Code: 10k0; Tolerance_%: 1; Power_W: 0.063; VDC_V: 50; TempCo: 100 ppm/C; EIA_Code: E96; U/M: EA
R32-R34 R39 R43 R44 R107 = CRCW040210K0FKED: RES, 10.0k ohm, 1%, 0.063W, 0402; Manufacturer: Vishay-Dale; CompType: Resistor; Res_ohm: 10000; Value_Code: 10k0; Tolerance_%: 1; Power_W: 0.063; VDC_V: 50; TempCo: 100 ppm/C; EIA_Code: E96; U/M: EA
R35 = CRCW120618R0JNEA: RES, DNP, 5%, 0.25W, 1206; Manufacturer: Vishay-Dale; CompType: Resistor; Res_ohm: 18; Value_Code: 18R0; Tolerance_%: 5; Power_W: 0.25; VDC_V: 200; TempCo: 200 ppm/C; EIA_Code: E24; U/M: EA
R36-R38 R46 R47 = ERJ14NF1001U: RES, DNP, 1%, 0.5W, 1210; Manufacturer: Panasonic; CompType: Resistor; Res_ohm: 1000; Tolerance_%: 1; Power_W: 0.5; VDC_V: 22; TempCo: 100 ppm/C; EIA_Code: E96; U/M: EA
R45 = CRCW120618R0JNEA: RES, DNP, 5%, 0.25W, 1206; Manufacturer: Vishay-Dale; CompType: Resistor; Res_ohm: 36; Value_Code: 36R0; Tolerance_%: 5; Power_W: 0.25; VDC_V: 200; TempCo: 200 ppm/C; EIA_Code: E24; U/M: EA
R48 = CRCW1206180RJNEA: RES, DNP, 5%, 0.25W, 1206; Manufacturer: Vishay-Dale; CompType: Resistor; Res_ohm: 180; Value_Code: 180R; Tolerance_%: 5; Power_W: 0.25; VDC_V: 200; TempCo: 200 ppm/C; EIA_Code: E24; U/M: EA
U1 U2 = TPS22993RLW: Quad Channel Load Switch with GPIO and I2C Control, RLW0020A; Alternate Manufacturer: None; Manufacturer: Texas Instruments; SymbolCreator: a0411947; CompType: IC; U/M: EA
U1_V1(1.8V) U2_V1(1.8V) U8_PVIN = 5005: as BATT+ on sheet Skylake_Hardware
U8 = TPS62151RGTT: Buck Step Down Regulator with 3 to 17 V Input and 1.8 V Output, -40 to 85 degC, 16-Pin QFN (RGT), Green (RoHS & no Sb/Br); Manufacturer: Texas Instruments; Alternate Manufacturer: None; Alternate PartNumber: Equivalent; Duty Cycle(Max)(%): 90; Iout(Max)(A): 1; Iq(Typ)(mA): 0.017; Preset Vout(V): 1.8; Rating: Catalog; SubFamily: Step-Down Regulator; Switch Current Limit(Typ)(A): 1.7; Synchronous Rectification: TRUE; Vin(Max)(V): 17; Vin(Min)(V): 3
V1.8Dx_3G4G_[1.8V,0.07A] V1.8Dx_AUDIO_[1.8V,0.13A] V1.8Dx_SENSORS_[1.8V,0.07A] V1.8Dx_SSD_[1.8V,0.07A] V1.8Dx_USBSDIO_[1.8V,0.05A] V1.8Dx_WIFI_[1.8V,0.07A] V1.8M_[1.8V,0.01A] V1.8S_[1.8V,0.10A] = 5008: Test Point, Compact, Orange, TH; Manufacturer: Keystone; CompType: Test Point Loop; U/M: EA

## Sheet Skylake_TPS22993_U3_U4.SchDoc
size 431 x 279 mm; Date: Not shown in title block; ApprovedBy: Not shown in title block; CheckedBy: Not shown in title block; Author: Not shown in title block; CompanyName: Not shown in title block; Engineer: Not shown in title block; Organization: Not shown in title block; Address1: Not shown in title block; Address2: Not shown in title block; Address3: Not shown in title block; Address4: Not shown in title block; DocumentNumber: 1; Revision: Use project parameter SCH_Rev; SheetNumber: 5; SheetTotal: 9; PageSetup: Record=PageOptions|CenterHorizontal=True|CenterVertical=True|PrintScale=1.00|XCorrection=1.00|YCorrection=1.00|PrintKind=0|BorderSize=5000000|LeftOffset=0|BottomOffset=0|Orientation=2|PaperLength=1000|PaperWidth=1000|Scale=100|PaperSource=15|PrintQuality=600|MediaType=1|DitherType=10|PaperKind=Letter|PrintScaleMode=1
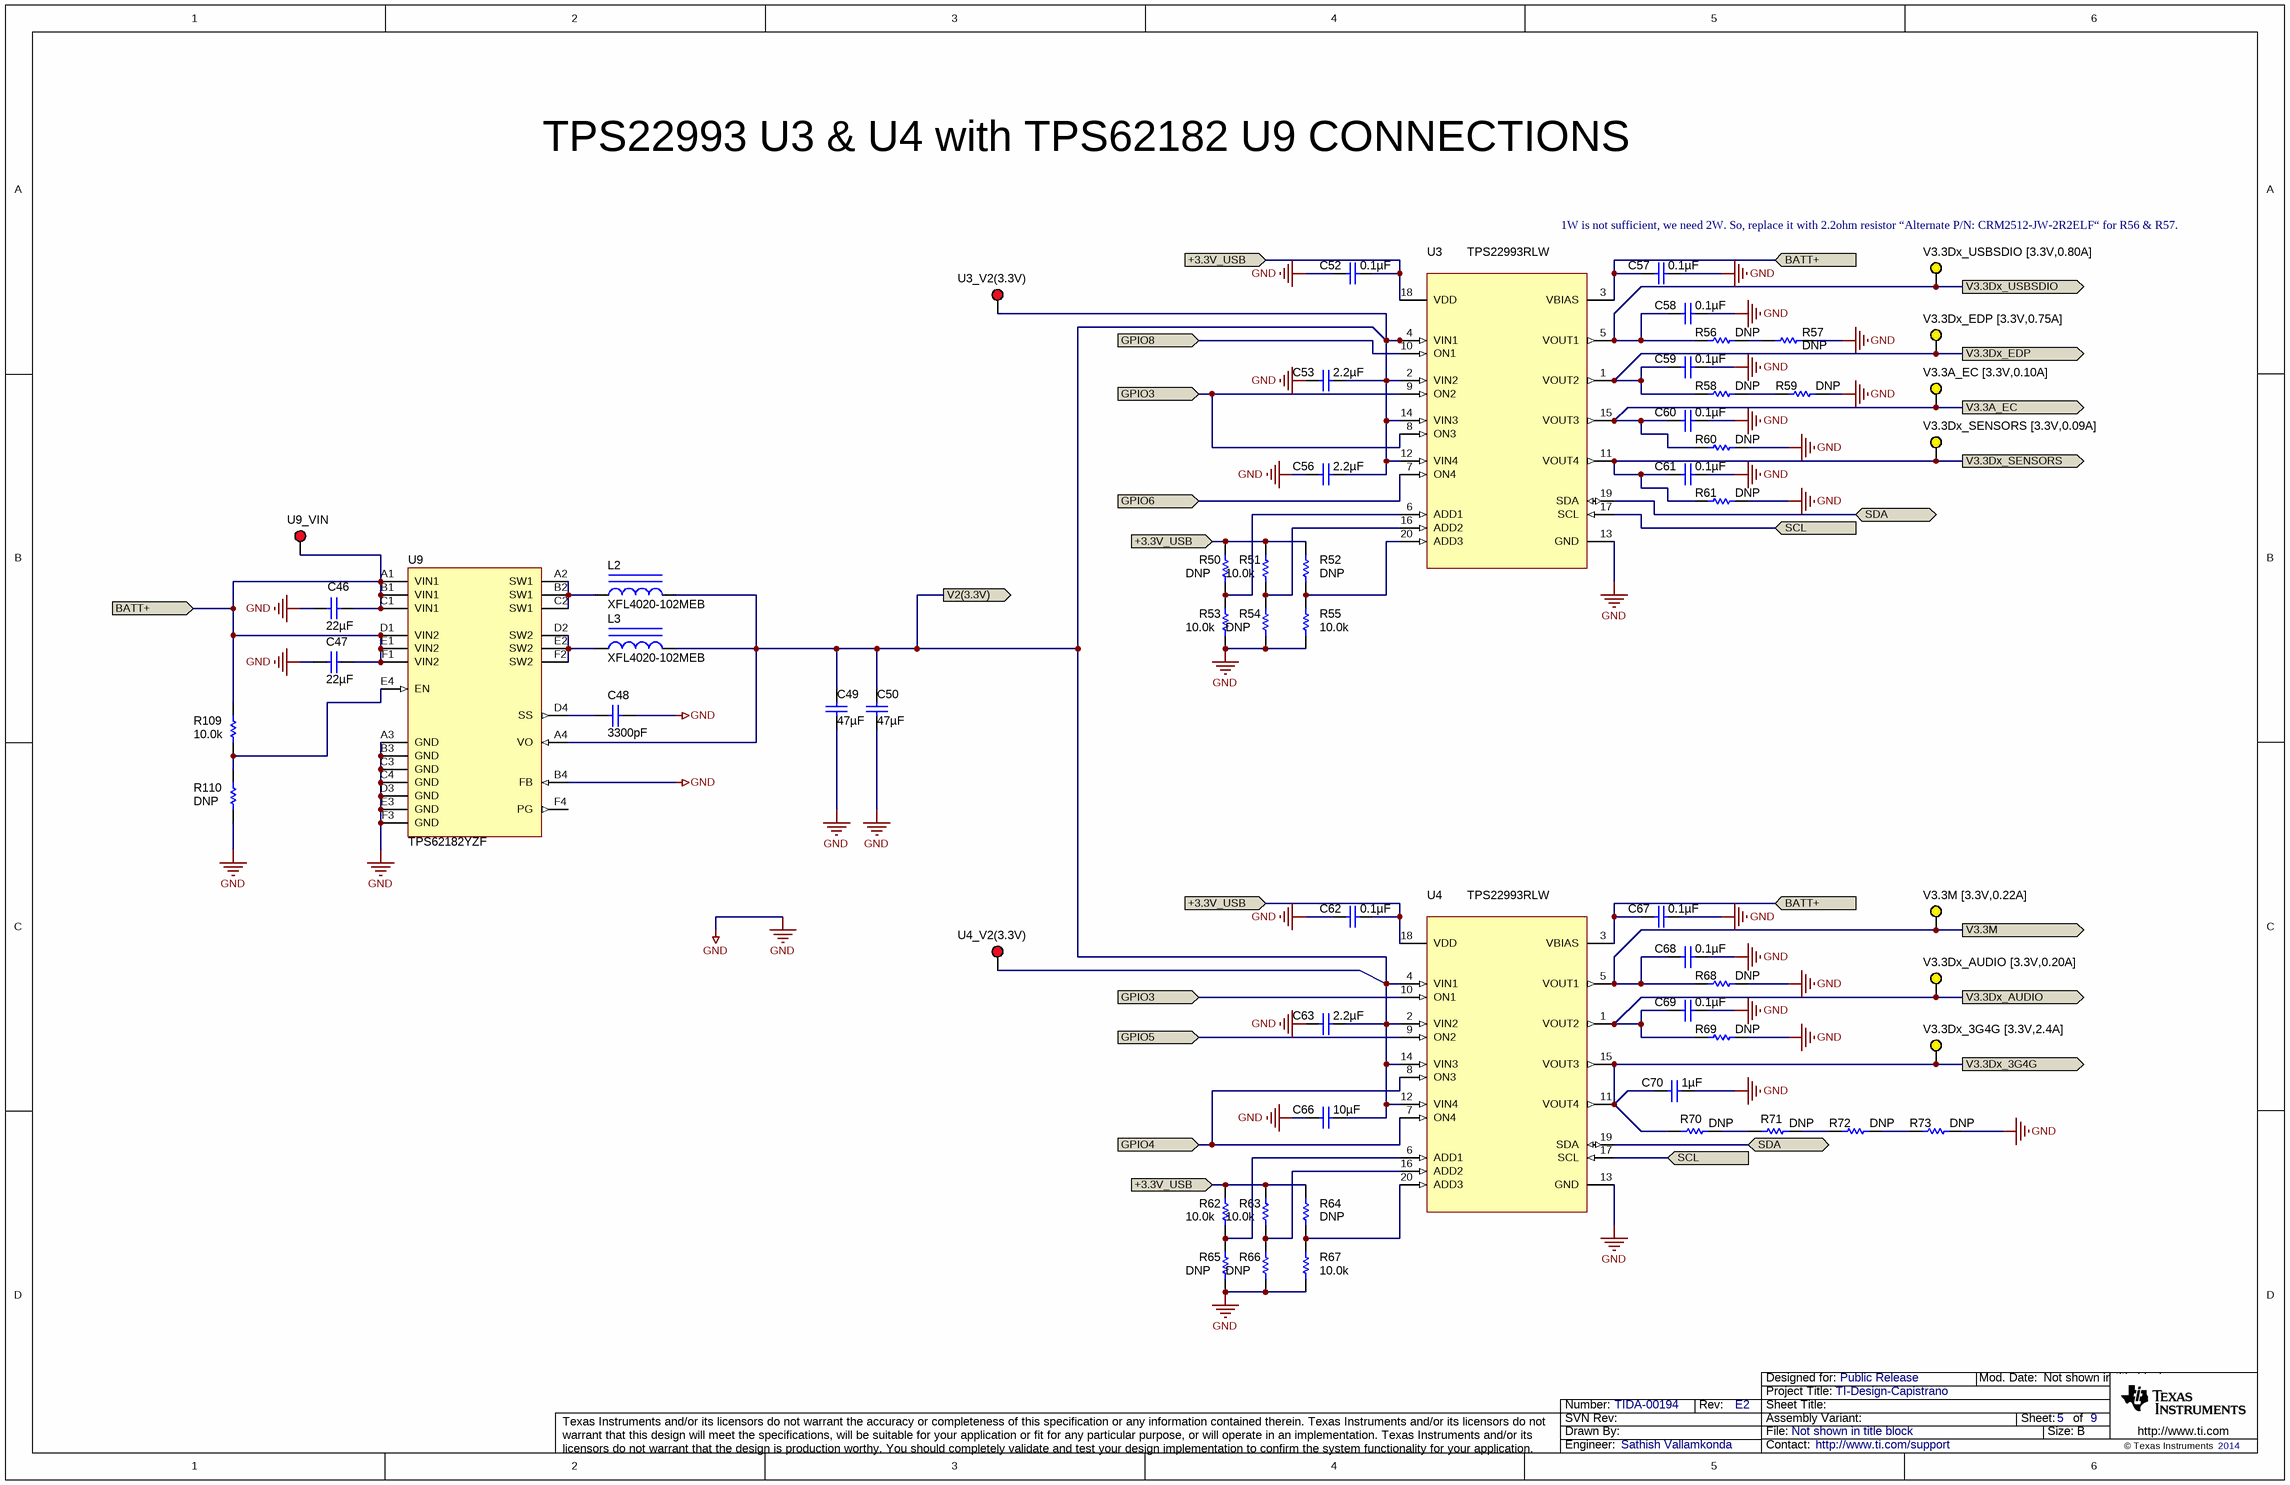
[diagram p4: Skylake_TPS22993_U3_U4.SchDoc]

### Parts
C46  ValueDisplayed: 22µF  [0805_HV]  (hidden comment: C2012JB1V226M125AC)
C47  ValueDisplayed: 22µF  [0805_HV]  (hidden comment: C2012JB1V226M125AC)
C48  ValueDisplayed: 3300pF  [0603]  (hidden comment: C0603C332J3RACTU)
C49  ValueDisplayed: 47µF  [0805_HV]  (hidden comment: C2012X5R1A476M125AC)
C50  ValueDisplayed: 47µF  [0805_HV]  (hidden comment: C2012X5R1A476M125AC)
C52  ValueDisplayed: 0.1µF  [0603]  (hidden comment: C0603C104K8RACTU)
C53  ValueDisplayed: 2.2µF  [0603]  (hidden comment: GRM188C81A225KE34D)
C56  ValueDisplayed: 2.2µF  [0603]  (hidden comment: GRM188C81A225KE34D)
C57  ValueDisplayed: 0.1µF  [0805_HV]  (hidden comment: GMK212BJ104KGHT)
C58  ValueDisplayed: 0.1µF  [0603]  (hidden comment: C0603C104K8RACTU)
C59  ValueDisplayed: 0.1µF  [0603]  (hidden comment: C0603C104K8RACTU)
C60  ValueDisplayed: 0.1µF  [0603]  (hidden comment: C0603C104K8RACTU)
C61  ValueDisplayed: 0.1µF  [0603]  (hidden comment: C0603C104K8RACTU)
C62  ValueDisplayed: 0.1µF  [0603]  (hidden comment: C0603C104K8RACTU)
C63  ValueDisplayed: 2.2µF  [0603]  (hidden comment: GRM188C81A225KE34D)
C66  ValueDisplayed: 10µF  [0805_HV]  (hidden comment: C2012JB1V106K085AC)
C67  ValueDisplayed: 0.1µF  [0805_HV]  (hidden comment: GMK212BJ104KGHT)
C68  ValueDisplayed: 0.1µF  [0603]  (hidden comment: C0603C104K8RACTU)
C69  ValueDisplayed: 0.1µF  [0603]  (hidden comment: C0603C104K8RACTU)
C70  ValueDisplayed: 1µF  [0603]  (hidden comment: C0603C105K8PACTU)
L2  XFL4020-102MEB  [XFL4020]
L3  XFL4020-102MEB  [XFL4020]
R50  value DNP  [0402]  (hidden comment: CRCW040210K0FKED)
R51  value 10.0k  [0402]  (hidden comment: CRCW040210K0FKED)
R52  value DNP  [0402]  (hidden comment: CRCW040210K0FKED)
R53  value 10.0k  [0402]  (hidden comment: CRCW040210K0FKED)
R54  value DNP  [0402]  (hidden comment: CRCW040210K0FKED)
R55  value 10.0k  [0402]  (hidden comment: CRCW040210K0FKED)
R56  value DNP  [2512M]  (hidden comment: CRM2512-JW-2R2ELF)
R57  value DNP  [2512M]  (hidden comment: CRM2512-JW-2R2ELF)
R58  value DNP  [2512M]  (hidden comment: CRM2512-JW-2R2ELF)
R59  value DNP  [2512M]  (hidden comment: CRM2512-JW-2R2ELF)
R60  value DNP  [2512M]  (hidden comment: RMCF2512JT33R0)
R61  value DNP  [2512M]  (hidden comment: CRCW251236R5FKEG)
R62  value 10.0k  [0402]  (hidden comment: CRCW040210K0FKED)
R63  value 10.0k  [0402]  (hidden comment: CRCW040210K0FKED)
R64  value DNP  [0402]  (hidden comment: CRCW040210K0FKED)
R65  value DNP  [0402]  (hidden comment: CRCW040210K0FKED)
R66  value DNP  [0402]  (hidden comment: CRCW040210K0FKED)
R67  value 10.0k  [0402]  (hidden comment: CRCW040210K0FKED)
R68  value DNP  [2512M]  (hidden comment: CRCW251215R0FKEG)
R69  value DNP  [2512M]  (hidden comment: RMCF2512FT16R5)
R70  value DNP  [PWR5322]  (hidden comment: PWR5322WR500JE)
R71  value DNP  [PWR5322]  (hidden comment: PWR5322WR500JE)
R72  value DNP  [2512M]  (hidden comment: RLP73K3AR22JTE)
R73  value DNP  [2512M]  (hidden comment: RLP73K3AR22JTE)
R109  value 10.0k  [0402]  (hidden comment: CRCW040210K0FKED)
R110  value DNP  [0402]  (hidden comment: CRCW040210K0FKED)
U3  TPS22993RLW  [RLW0020A]
U3_V2(3.3V)  5005  [Keystone5005]  (value not drawn)
U4  TPS22993RLW  [RLW0020A]
U4_V2(3.3V)  5005  [Keystone5005]  (value not drawn)
U9  TPS62182YZF  [YZF0024AMAM]
U9_VIN  5005  [Keystone5005]  (value not drawn)
V3.3A_EC_[3.3V,0.10A]  5009  [Keystone5009]  (value not drawn)
V3.3Dx_3G4G_[3.3V,2.4A]  5009  [Keystone5009]  (value not drawn)
V3.3Dx_AUDIO_[3.3V,0.20A]  5009  [Keystone5009]  (value not drawn)
V3.3Dx_EDP_[3.3V,0.75A]  5009  [Keystone5009]  (value not drawn)
V3.3Dx_SENSORS_[3.3V,0.09A]  5009  [Keystone5009]  (value not drawn)
V3.3Dx_USBSDIO_[3.3V,0.80A]  5009  [Keystone5009]  (value not drawn)
V3.3M_[3.3V,0.22A]  5009  [Keystone5009]  (value not drawn)

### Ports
+3.3V_USB (in), BATT+ (in), GPIO3 (in), GPIO4 (in), GPIO5 (in), GPIO6 (in), GPIO8 (in), SCL (in), SDA (bidir), V2(3.3V) (out), V3.3A_EC (out), V3.3Dx_3G4G (out), V3.3Dx_AUDIO (out), V3.3Dx_EDP (out), V3.3Dx_SENSORS (out), V3.3Dx_USBSDIO (out), V3.3M (out)

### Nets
GND: C46.2 C47.2 C48.1 C49.2 C50.2 C52.2 C53.2 C56.2 C57.1 C58.1 C59.1 C60.1 C61.1 C62.2 C63.2 C66.2 C67.1 C68.1 C69.1 C70.1 R53.1 R54.1 R55.1 R57.2 R59.2 R60.2 R61.2 R65.1 R66.1 R67.1 R68.2 R69.2 R73.2 R110.1 U3.13(GND) U4.13(GND) U9.A3(GND) U9.B3(GND) U9.B4(FB) U9.C3(GND) U9.C4(GND) U9.D3(GND) U9.E3(GND) U9.F3(GND)
+3.3V_USB: C52.1 C62.1 R50.2 R51.2 R52.2 R62.2 R63.2 R64.2 U3.18(VDD) U4.18(VDD) ; port +3.3V_USB
BATT+: C46.1 C47.1 C57.2 C67.2 R109.2 U3.3(VBIAS) U4.3(VBIAS) U9.A1(VIN1) U9.B1(VIN1) U9.C1(VIN1) U9.D1(VIN2) U9.E1(VIN2) U9.F1(VIN2) U9_VIN.1 ; port BATT+
GPIO3: U3.8(ON3) U3.9(ON2) U4.10(ON1) ; port GPIO3
GPIO4: U4.7(ON4) U4.8(ON3) ; port GPIO4
GPIO5: U4.9(ON2) ; port GPIO5
GPIO6: U3.7(ON4) ; port GPIO6
GPIO8: U3.10(ON1) ; port GPIO8
SCL: U3.17(SCL) U4.17(SCL) ; port SCL
SDA: U3.19(SDA) U4.19(SDA) ; port SDA
V2(3.3V): C49.1 C50.1 C53.1 C56.1 C63.1 C66.1 L2.2 L3.2 U3.2(VIN2) U3.4(VIN1) U3.12(VIN4) U3.14(VIN3) U3_V2(3.3V).1 U4.2(VIN2) U4.4(VIN1) U4.12(VIN4) U4.14(VIN3) U4_V2(3.3V).1 U9.A4(VO) ; port V2(3.3V)
V3.3A_EC: C60.2 R60.1 U3.15(VOUT3) V3.3A_EC_[3.3V,0.10A].1 ; port V3.3A_EC
V3.3Dx_3G4G: C70.2 R70.1 U4.11(VOUT4) U4.15(VOUT3) V3.3Dx_3G4G_[3.3V,2.4A].1 ; port V3.3Dx_3G4G
V3.3Dx_AUDIO: C69.2 R69.1 U4.1(VOUT2) V3.3Dx_AUDIO_[3.3V,0.20A].1 ; port V3.3Dx_AUDIO
V3.3Dx_EDP: C59.2 R58.1 U3.1(VOUT2) V3.3Dx_EDP_[3.3V,0.75A].1 ; port V3.3Dx_EDP
V3.3Dx_SENSORS: C61.2 R61.1 U3.11(VOUT4) V3.3Dx_SENSORS_[3.3V,0.09A].1 ; port V3.3Dx_SENSORS
V3.3Dx_USBSDIO: C58.2 R56.1 U3.5(VOUT1) V3.3Dx_USBSDIO_[3.3V,0.80A].1 ; port V3.3Dx_USBSDIO
V3.3M: C68.2 R68.1 U4.5(VOUT1) V3.3M_[3.3V,0.22A].1 ; port V3.3M
NetC48_2: C48.2 U9.D4(SS)
NetL2_1: L2.1 U9.A2(SW1) U9.B2(SW1) U9.C2(SW1)
NetL3_1: L3.1 U9.D2(SW2) U9.E2(SW2) U9.F2(SW2)
NetR50_1: R50.1 R53.2 U3.6(ADD1)
NetR51_1: R51.1 R54.2 U3.16(ADD2)
NetR52_1: R52.1 R55.2 U3.20(ADD3)
NetR56_2: R56.2 R57.1
NetR58_2: R58.2 R59.1
NetR62_1: R62.1 R65.2 U4.6(ADD1)
NetR63_1: R63.1 R66.2 U4.16(ADD2)
NetR64_1: R64.1 R67.2 U4.20(ADD3)
NetR70_2: R70.2 R71.1
NetR71_2: R71.2 R72.1
NetR72_2: R72.2 R73.1
NetR109_1: R109.1 R110.2 U9.E4(EN)

Not connected (* = marked no-connect by the designer): U9 F4(PG)

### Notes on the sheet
- TPS22993 U3 & U4 with TPS62182 U9 CONNECTIONS
- 1W is not sufficient, we need 2W. So, replace it with 2.2ohm resistor “Alternate P/N: CRM2512-JW-2R2ELF“ for R56 & R57.

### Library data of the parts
C46 C47 = GRM21BR61E226ME44: as C24 on sheet Skylake_TPS22993_U1_U2
C48 = C0603C332K5RACTU: as C23 on sheet Skylake_TPS22993_U1_U2
C49 C50 = GRM21BR61E226ME44: CAP, CERM, 47uF, 10V, +/-20%, X5R, 0805; Manufacturer: TDK Corporation; Polarized: N; CompType: Capacitor; U/M: EA; Cap_F: 0.000022; Tolerance_%: 20; Value1: Unknown; VDC_V: 10; TaMin_C: -55; TaMax_C: 85; Cap_Case: 0805
C52 C58-C62 C68 C69 = GRM188R71C104KA01D: as C8 on sheet Skylake_Hardware
C53 C56 C63 = GRM188C81A225KE34D: as C27 on sheet Skylake_TPS22993_U1_U2
C57 C67 = GRM21BR61E226ME44: as C31 on sheet Skylake_TPS22993_U1_U2
C66 = GRM21BR61E226ME44: CAP, CERM, 10uF, 35V, +/-10%, X5R, 0805; Manufacturer: TDK Corporation; Polarized: N; CompType: Capacitor; U/M: EA; Cap_F: 0.000022; Tolerance_%: 20; Value1: Unknown; VDC_V: 35; TaMin_C: -55; TaMax_C: 85; Cap_Case: 0805
C70 = C0603C105K8PACTU: CAP, CERM, 1uF, 10V, +/-10%, X5R, 0603; Manufacturer: Kemet; Polarized: N; CompType: Capacitor; U/M: EA; Cap_F: 0.000001; Tolerance_%: 10; Value1: Unknown; TaMin_C: -55; TaMax_C: 85
L2 L3 = XFL4020-102MEB: Inductor, Shielded, Composite, 1uH, 5.4A, 0.01 ohm, SMD; Manufacturer: Coilcraft; Ind_H: 1.0E-6; ValueDisplayed: 1µH; Imax_A: 5.4; Irms: 11A @ 40C rise; Isat: 5.4A @ 30% inductance drop; DCR_ohm: 0.01; U/M: EA
R50 R52 R54 R64-R66 R110 = CRCW040210K0FKED: as R29 on sheet Skylake_TPS22993_U1_U2
R51 R53 R55 R62 R63 R67 R109 = CRCW040210K0FKED: as R32 on sheet Skylake_TPS22993_U1_U2
R56 = CSNL2512FT2L00: RES, DNP, 5%, 2W, 2512; Manufacturer: Bourns Inc; CompType: Resistor; Res_ohm: 2.2; Tolerance_%: 5; Power_W: 2; VDC_V: 200; TempCo: 50 ppm/C; U/M: EA
R57 = CSNL2512FT2L00: RES, DNP, 1%, 2W, 2512; Manufacturer: Bourns Inc.; CompType: Resistor; Res_ohm: 2.2; Tolerance_%: 5; Power_W: 2; VDC_V: 200; TempCo: 50 ppm/C; U/M: EA
R58 R59 = CSNL2512FT2L00: RES, DNP, 5%, 2W, 2512; Manufacturer: Bourns Inc.; CompType: Resistor; Res_ohm: 2.2; Tolerance_%: 5; Power_W: 2; VDC_V: 200; TempCo: 50 ppm/C; U/M: EA
R60 = CSNL2512FT2L00: RES, DNP, 5%, 1W, 2512; Manufacturer: Stackpole Electronics Inc; CompType: Resistor; Res_ohm: 33; Tolerance_%: 1; VDC_V: 200; TempCo: 50 ppm/C; U/M: EA
R61 = CSNL2512FT2L00: RES, DNP, 1%, 1W, 2512; Manufacturer: Vishay Dale; CompType: Resistor; Res_ohm: 36.5; Tolerance_%: 1; VDC_V: 200; TempCo: 50 ppm/C; U/M: EA
R68 = CSNL2512FT2L00: RES, DNP, 1%, 1W, 2512; Manufacturer: Vishay Dale; CompType: Resistor; Res_ohm: 15; Tolerance_%: 1; VDC_V: 200; TempCo: 50 ppm/C; U/M: EA
R69 = CSNL2512FT2L00: RES, DNP, 1%, 1W, 2512; Manufacturer: Stackpole Electronics Inc; CompType: Resistor; Res_ohm: 16.5; Tolerance_%: 1; VDC_V: 200; TempCo: 50 ppm/C; U/M: EA
R70 R71 = PWR5322WR500JE: RES, DNP, 5%, 3W, 13.5x5.65x5.5mm; Manufacturer: Bourns; CompType: Resistor; Res_ohm: 0.5; Value_Code: R500; Tolerance_%: 5; Power_W: 3; TempCo: 90 ppm/C; U/M: EA
R72 R73 = CRCW25121K10JNEG: RES, DNP, 5%, 2W, 2512; Manufacturer: TE Connectivity; CompType: Resistor; Tolerance_%: 5; Power_W: 2; VDC_V: 500; TempCo: 200 ppm/C; EIA_Code: E24; U/M: EA
U3 U4 = TPS22993RLW: as U1 on sheet Skylake_TPS22993_U1_U2
U3_V2(3.3V) U4_V2(3.3V) U9_VIN = 5005: as BATT+ on sheet Skylake_Hardware
U9 = TPS62180YZF: 4 - 17V, 6A, 2-Phase Step-Down Converter, YZF0024AMAM; Alternate Manufacturer: None; Manufacturer: Texas Instruments; SymbolCreator: a0799628; CompType: IC; U/M: EA
V3.3A_EC_[3.3V,0.10A] V3.3Dx_3G4G_[3.3V,2.4A] V3.3Dx_AUDIO_[3.3V,0.20A] V3.3Dx_EDP_[3.3V,0.75A] V3.3Dx_SENSORS_[3.3V,0.09A] V3.3Dx_USBSDIO_[3.3V,0.80A] V3.3M_[3.3V,0.22A] = 5009: Test Point, Compact, Yellow, TH; Manufacturer: Keystone; CompType: Test Point Loop; U/M: EA

## Sheet Skylake_TPS22993_U5_U6.SchDoc
size 431 x 279 mm; Date: Not shown in title block; ApprovedBy: Not shown in title block; CheckedBy: Not shown in title block; Author: Not shown in title block; CompanyName: Not shown in title block; Engineer: Not shown in title block; Organization: Not shown in title block; Address1: Not shown in title block; Address2: Not shown in title block; Address3: Not shown in title block; Address4: Not shown in title block; DocumentNumber: 1; Revision: Use project parameter SCH_Rev; SheetNumber: 6; SheetTotal: 9; PageSetup: Record=PageOptions|CenterHorizontal=True|CenterVertical=True|PrintScale=1.00|XCorrection=1.00|YCorrection=1.00|PrintKind=0|BorderSize=5000000|LeftOffset=0|BottomOffset=0|Orientation=2|PaperLength=1000|PaperWidth=1000|Scale=100|PaperSource=15|PrintQuality=600|MediaType=1|DitherType=10|PaperKind=Letter|PrintScaleMode=1
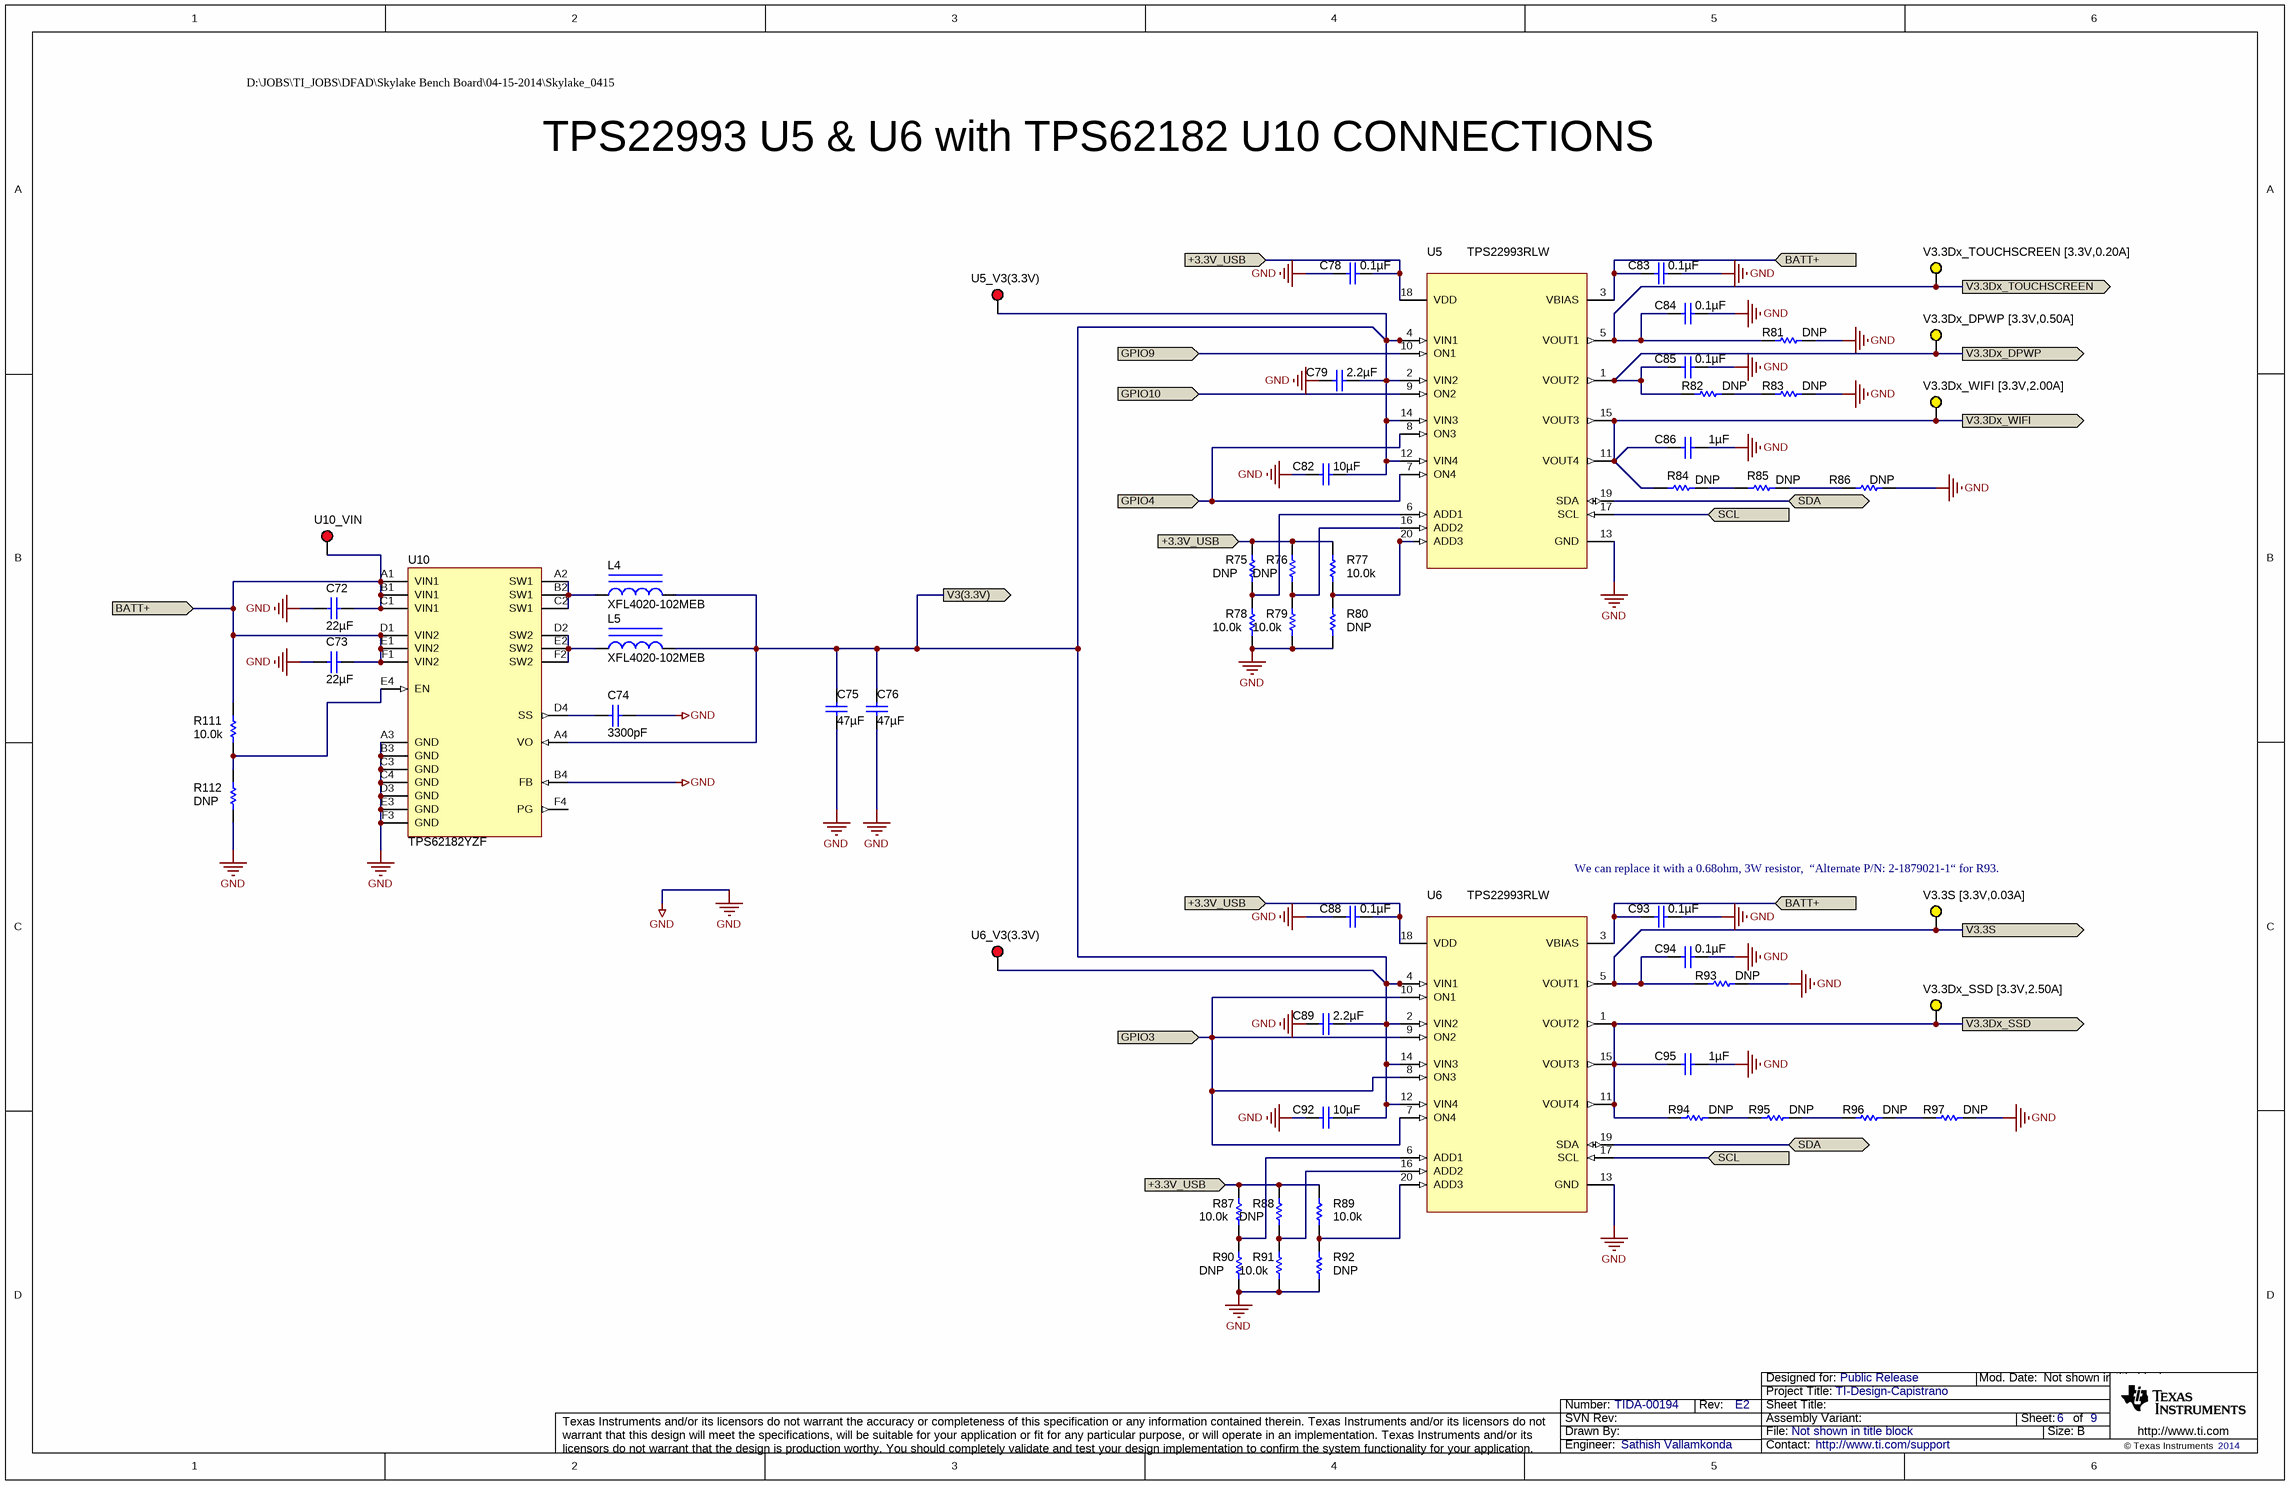
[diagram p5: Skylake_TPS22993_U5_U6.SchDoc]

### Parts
C72  ValueDisplayed: 22µF  [0805_HV]  (hidden comment: C2012JB1V226M125AC)
C73  ValueDisplayed: 22µF  [0805_HV]  (hidden comment: C2012JB1V226M125AC)
C74  ValueDisplayed: 3300pF  [0603]  (hidden comment: C0603C332J3RACTU)
C75  ValueDisplayed: 47µF  [0805_HV]  (hidden comment: C2012X5R1A476M125AC)
C76  ValueDisplayed: 47µF  [0805_HV]  (hidden comment: C2012X5R1A476M125AC)
C78  ValueDisplayed: 0.1µF  [0603]  (hidden comment: C0603C104K8RACTU)
C79  ValueDisplayed: 2.2µF  [0603]  (hidden comment: GRM188C81A225KE34D)
C82  ValueDisplayed: 10µF  [0805_HV]  (hidden comment: C2012JB1V106K085AC)
C83  ValueDisplayed: 0.1µF  [0805_HV]  (hidden comment: GMK212BJ104KGHT)
C84  ValueDisplayed: 0.1µF  [0603]  (hidden comment: C0603C104K8RACTU)
C85  ValueDisplayed: 0.1µF  [0603]  (hidden comment: C0603C104K8RACTU)
C86  ValueDisplayed: 1µF  [0603]  (hidden comment: C0603C105K8PACTU)
C88  ValueDisplayed: 0.1µF  [0603]  (hidden comment: C0603C104K8RACTU)
C89  ValueDisplayed: 2.2µF  [0603]  (hidden comment: GRM188C81A225KE34D)
C92  ValueDisplayed: 10µF  [0805_HV]  (hidden comment: C2012JB1V106K085AC)
C93  ValueDisplayed: 0.1µF  [0805_HV]  (hidden comment: GMK212BJ104KGHT)
C94  ValueDisplayed: 0.1µF  [0603]  (hidden comment: C0603C104K8RACTU)
C95  ValueDisplayed: 1µF  [0603]  (hidden comment: C0603C105K8PACTU)
L4  XFL4020-102MEB  [XFL4020]
L5  XFL4020-102MEB  [XFL4020]
R75  value DNP  [0402]  (hidden comment: CRCW040210K0FKED)
R76  value DNP  [0402]  (hidden comment: CRCW040210K0FKED)
R77  value 10.0k  [0402]  (hidden comment: CRCW040210K0FKED)
R78  value 10.0k  [0402]  (hidden comment: CRCW040210K0FKED)
R79  value 10.0k  [0402]  (hidden comment: CRCW040210K0FKED)
R80  value DNP  [0402]  (hidden comment: CRCW040210K0FKED)
R81  value DNP  [2512M]  (hidden comment: RMCF2512FT16R5)
R82  value DNP  [2512M]  (hidden comment: CRCW25123R30FKEGHP)
R83  value DNP  [2512M]  (hidden comment: CRCW25123R30FKEGHP)
R84  value DNP  [PWR5322]  (hidden comment: PWR5322WR500JE)
R85  value DNP  [PWR5322]  (hidden comment: PWR5322WR500JE)
R86  value DNP  [SM_3]  (hidden comment: 2-1879021-1)
R87  value 10.0k  [0402]  (hidden comment: CRCW040210K0FKED)
R88  value DNP  [0402]  (hidden comment: CRCW040210K0FKED)
R89  value 10.0k  [0402]  (hidden comment: CRCW040210K0FKED)
R90  value DNP  [0402]  (hidden comment: CRCW040210K0FKED)
R91  value 10.0k  [0402]  (hidden comment: CRCW040210K0FKED)
R92  value DNP  [0402]  (hidden comment: CRCW040210K0FKED)
R93  value DNP  [1206]  (hidden comment: CRCW1206110RJNEA)
R94  value DNP  [SM_3]  (hidden comment: A103634CT)
R95  value DNP  [SM_3]  (hidden comment: A103634CT)
R96  value DNP  [SM_3]  (hidden comment: A103634CT)
R97  value DNP  [SM_3]  (hidden comment: A103634CT)
R111  value 10.0k  [0402]  (hidden comment: CRCW040210K0FKED)
R112  value DNP  [0402]  (hidden comment: CRCW040210K0FKED)
U5  TPS22993RLW  [RLW0020A]
U5_V3(3.3V)  5005  [Keystone5005]  (value not drawn)
U6  TPS22993RLW  [RLW0020A]
U6_V3(3.3V)  5005  [Keystone5005]  (value not drawn)
U10  TPS62182YZF  [YZF0024AMAM]
U10_VIN  5005  [Keystone5005]  (value not drawn)
V3.3Dx_DPWP_[3.3V,0.50A]  5009  [Keystone5009]  (value not drawn)
V3.3Dx_SSD_[3.3V,2.50A]  5009  [Keystone5009]  (value not drawn)
V3.3Dx_TOUCHSCREEN_[3.3V,0.20A]  5009  [Keystone5009]  (value not drawn)
V3.3Dx_WIFI_[3.3V,2.00A]  5009  [Keystone5009]  (value not drawn)
V3.3S_[3.3V,0.03A]  5009  [Keystone5009]  (value not drawn)

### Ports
+3.3V_USB (in), BATT+ (in), GPIO3 (in), GPIO4 (in), GPIO9 (in), GPIO10 (in), SCL (in), SDA (bidir), V3(3.3V) (out), V3.3Dx_DPWP (out), V3.3Dx_SSD (out), V3.3Dx_TOUCHSCREEN (out), V3.3Dx_WIFI (out), V3.3S (out)

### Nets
GND: C72.2 C73.2 C74.1 C75.2 C76.2 C78.2 C79.2 C82.2 C83.1 C84.1 C85.1 C86.1 C88.2 C89.2 C92.2 C93.1 C94.1 C95.1 R78.1 R79.1 R80.1 R81.2 R83.2 R86.2 R90.1 R91.1 R92.1 R93.2 R97.2 R112.1 U5.13(GND) U6.13(GND) U10.A3(GND) U10.B3(GND) U10.B4(FB) U10.C3(GND) U10.C4(GND) U10.D3(GND) U10.E3(GND) U10.F3(GND)
+3.3V_USB: C78.1 C88.1 R75.2 R76.2 R77.2 R87.2 R88.2 R89.2 U5.18(VDD) U6.18(VDD) ; port +3.3V_USB
BATT+: C72.1 C73.1 C83.2 C93.2 R111.2 U5.3(VBIAS) U6.3(VBIAS) U10.A1(VIN1) U10.B1(VIN1) U10.C1(VIN1) U10.D1(VIN2) U10.E1(VIN2) U10.F1(VIN2) U10_VIN.1 ; port BATT+
GPIO3: U6.7(ON4) U6.8(ON3) U6.9(ON2) U6.10(ON1) ; port GPIO3
GPIO4: U5.7(ON4) U5.8(ON3) ; port GPIO4
GPIO9: U5.10(ON1) ; port GPIO9
GPIO10: U5.9(ON2) ; port GPIO10
SCL: U5.17(SCL) U6.17(SCL) ; port SCL
SDA: U5.19(SDA) U6.19(SDA) ; port SDA
V3(3.3V): C75.1 C76.1 C79.1 C82.1 C89.1 C92.1 L4.2 L5.2 U5.2(VIN2) U5.4(VIN1) U5.12(VIN4) U5.14(VIN3) U5_V3(3.3V).1 U6.2(VIN2) U6.4(VIN1) U6.12(VIN4) U6.14(VIN3) U6_V3(3.3V).1 U10.A4(VO) ; port V3(3.3V)
V3.3Dx_DPWP: C85.2 R82.1 U5.1(VOUT2) V3.3Dx_DPWP_[3.3V,0.50A].1 ; port V3.3Dx_DPWP
V3.3Dx_SSD: C95.2 R94.1 U6.1(VOUT2) U6.11(VOUT4) U6.15(VOUT3) V3.3Dx_SSD_[3.3V,2.50A].1 ; port V3.3Dx_SSD
V3.3Dx_TOUCHSCREEN: C84.2 R81.1 U5.5(VOUT1) V3.3Dx_TOUCHSCREEN_[3.3V,0.20A].1 ; port V3.3Dx_TOUCHSCREEN
V3.3Dx_WIFI: C86.2 R84.1 U5.11(VOUT4) U5.15(VOUT3) V3.3Dx_WIFI_[3.3V,2.00A].1 ; port V3.3Dx_WIFI
V3.3S: C94.2 R93.1 U6.5(VOUT1) V3.3S_[3.3V,0.03A].1 ; port V3.3S
NetC74_2: C74.2 U10.D4(SS)
NetL4_1: L4.1 U10.A2(SW1) U10.B2(SW1) U10.C2(SW1)
NetL5_1: L5.1 U10.D2(SW2) U10.E2(SW2) U10.F2(SW2)
NetR75_1: R75.1 R78.2 U5.6(ADD1)
NetR76_1: R76.1 R79.2 U5.16(ADD2)
NetR77_1: R77.1 R80.2 U5.20(ADD3)
NetR82_2: R82.2 R83.1
NetR84_2: R84.2 R85.1
NetR85_2: R85.2 R86.1
NetR87_1: R87.1 R90.2 U6.6(ADD1)
NetR88_1: R88.1 R91.2 U6.16(ADD2)
NetR89_1: R89.1 R92.2 U6.20(ADD3)
NetR94_2: R94.2 R95.1
NetR95_2: R95.2 R96.1
NetR96_2: R96.2 R97.1
NetR111_1: R111.1 R112.2 U10.E4(EN)

Not connected (* = marked no-connect by the designer): U10 F4(PG)

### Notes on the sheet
- D:\JOBS\TI_JOBS\DFAD\Skylake Bench Board\04-15-2014\Skylake_0415
- TPS22993 U5 & U6 with TPS62182 U10 CONNECTIONS
- We can replace it with a 0.68ohm, 3W resistor,  “Alternate P/N: 2-1879021-1“ for R93.

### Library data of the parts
C72 C73 = GRM21BR61E226ME44: as C24 on sheet Skylake_TPS22993_U1_U2
C74 = C0603C332K5RACTU: as C23 on sheet Skylake_TPS22993_U1_U2
C75 C76 = GRM21BR61E226ME44: as C49 on sheet Skylake_TPS22993_U3_U4
C78 C84 C85 C88 C94 = GRM188R71C104KA01D: as C8 on sheet Skylake_Hardware
C79 C89 = GRM188C81A225KE34D: as C27 on sheet Skylake_TPS22993_U1_U2
C82 C92 = GRM21BR61E226ME44: as C66 on sheet Skylake_TPS22993_U3_U4
C83 C93 = GRM21BR61E226ME44: as C31 on sheet Skylake_TPS22993_U1_U2
C86 C95 = C0603C105K8PACTU: as C70 on sheet Skylake_TPS22993_U3_U4
L4 L5 = XFL4020-102MEB: as L2 on sheet Skylake_TPS22993_U3_U4
R75 R76 R80 R88 R90 R92 R112 = CRCW040210K0FKED: as R29 on sheet Skylake_TPS22993_U1_U2
R77-R79 R87 R89 R91 R111 = CRCW040210K0FKED: as R32 on sheet Skylake_TPS22993_U1_U2
R81 = CSNL2512FT2L00: as R69 on sheet Skylake_TPS22993_U3_U4
R82 R83 = CRCW25121K10JNEG: RES, DNP, 5%, 1.5W, 2512; Manufacturer: Vishay-Dale; CompType: Resistor; Tolerance_%: 5; Power_W: 1; VDC_V: 500; TempCo: 200 ppm/C; EIA_Code: E24; U/M: EA
R84 R85 = PWR5322WR500JE: as R70 on sheet Skylake_TPS22993_U3_U4
R86 = SMW31R0JT: RES, DNP, 5%, 3W, SM_3, 10.5x5x5.5mm; Manufacturer: TE Connectivity; CompType: Resistor; Res_ohm: 0.68; Tolerance_%: 5; Power_W: 3; VDC_V: 500; TempCo: 200 ppm/C; EIA_Code: E24; U/M: EA
R93 = CRCW1206110RJNEA: RES, DNP, 5%, 0.25W, 1206; Manufacturer: Vishay-Dale; CompType: Resistor; Res_ohm: 110; Value_Code: 110R; Tolerance_%: 5; Power_W: 0.25; VDC_V: 200; TempCo: 200 ppm/C; EIA_Code: E24; U/M: EA
R94-R97 = SMW31R0JT: RES, DNP, 5%, 3W, SM_3, 10.5x5x5.5mm; Manufacturer: TE Connectivity; CompType: Resistor; Res_ohm: 1; Tolerance_%: 5; Power_W: 3; VDC_V: 500; TempCo: 200 ppm/C; EIA_Code: E24; U/M: EA
U5 U6 = TPS22993RLW: as U1 on sheet Skylake_TPS22993_U1_U2
U5_V3(3.3V) U6_V3(3.3V) U10_VIN = 5005: as BATT+ on sheet Skylake_Hardware
U10 = TPS62180YZF: as U9 on sheet Skylake_TPS22993_U3_U4
V3.3Dx_DPWP_[3.3V,0.50A] V3.3Dx_SSD_[3.3V,2.50A] V3.3Dx_TOUCHSCREEN_[3.3V,0.20A] V3.3Dx_WIFI_[3.3V,2.00A] V3.3S_[3.3V,0.03A] = 5009: as V3.3A_EC_[3.3V,0.10A] on sheet Skylake_TPS22993_U3_U4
